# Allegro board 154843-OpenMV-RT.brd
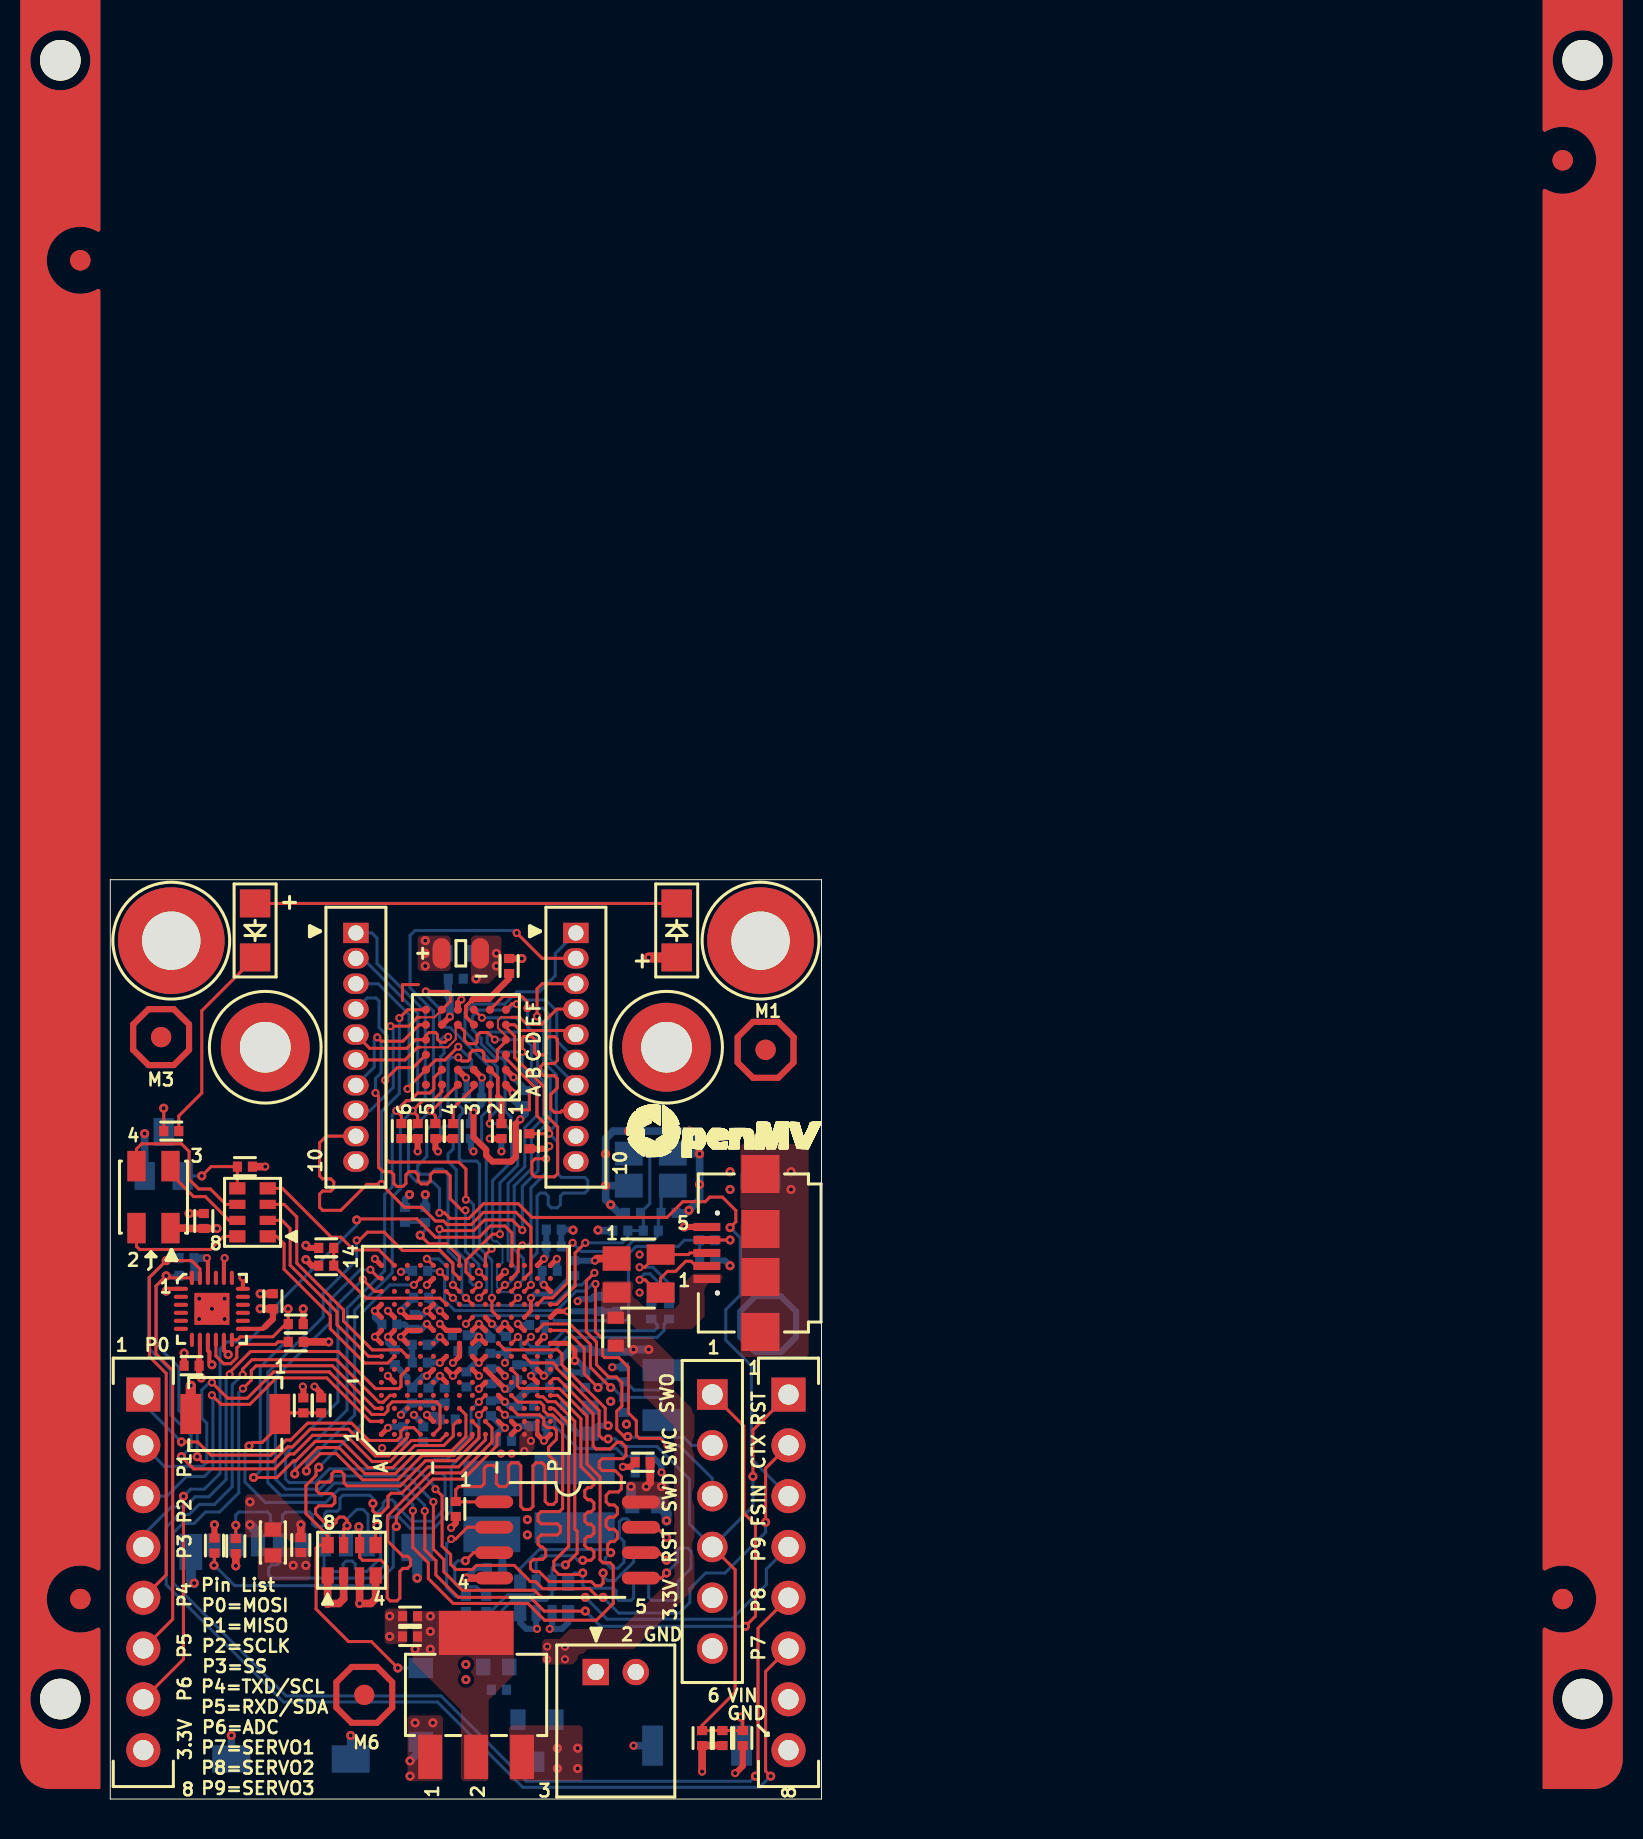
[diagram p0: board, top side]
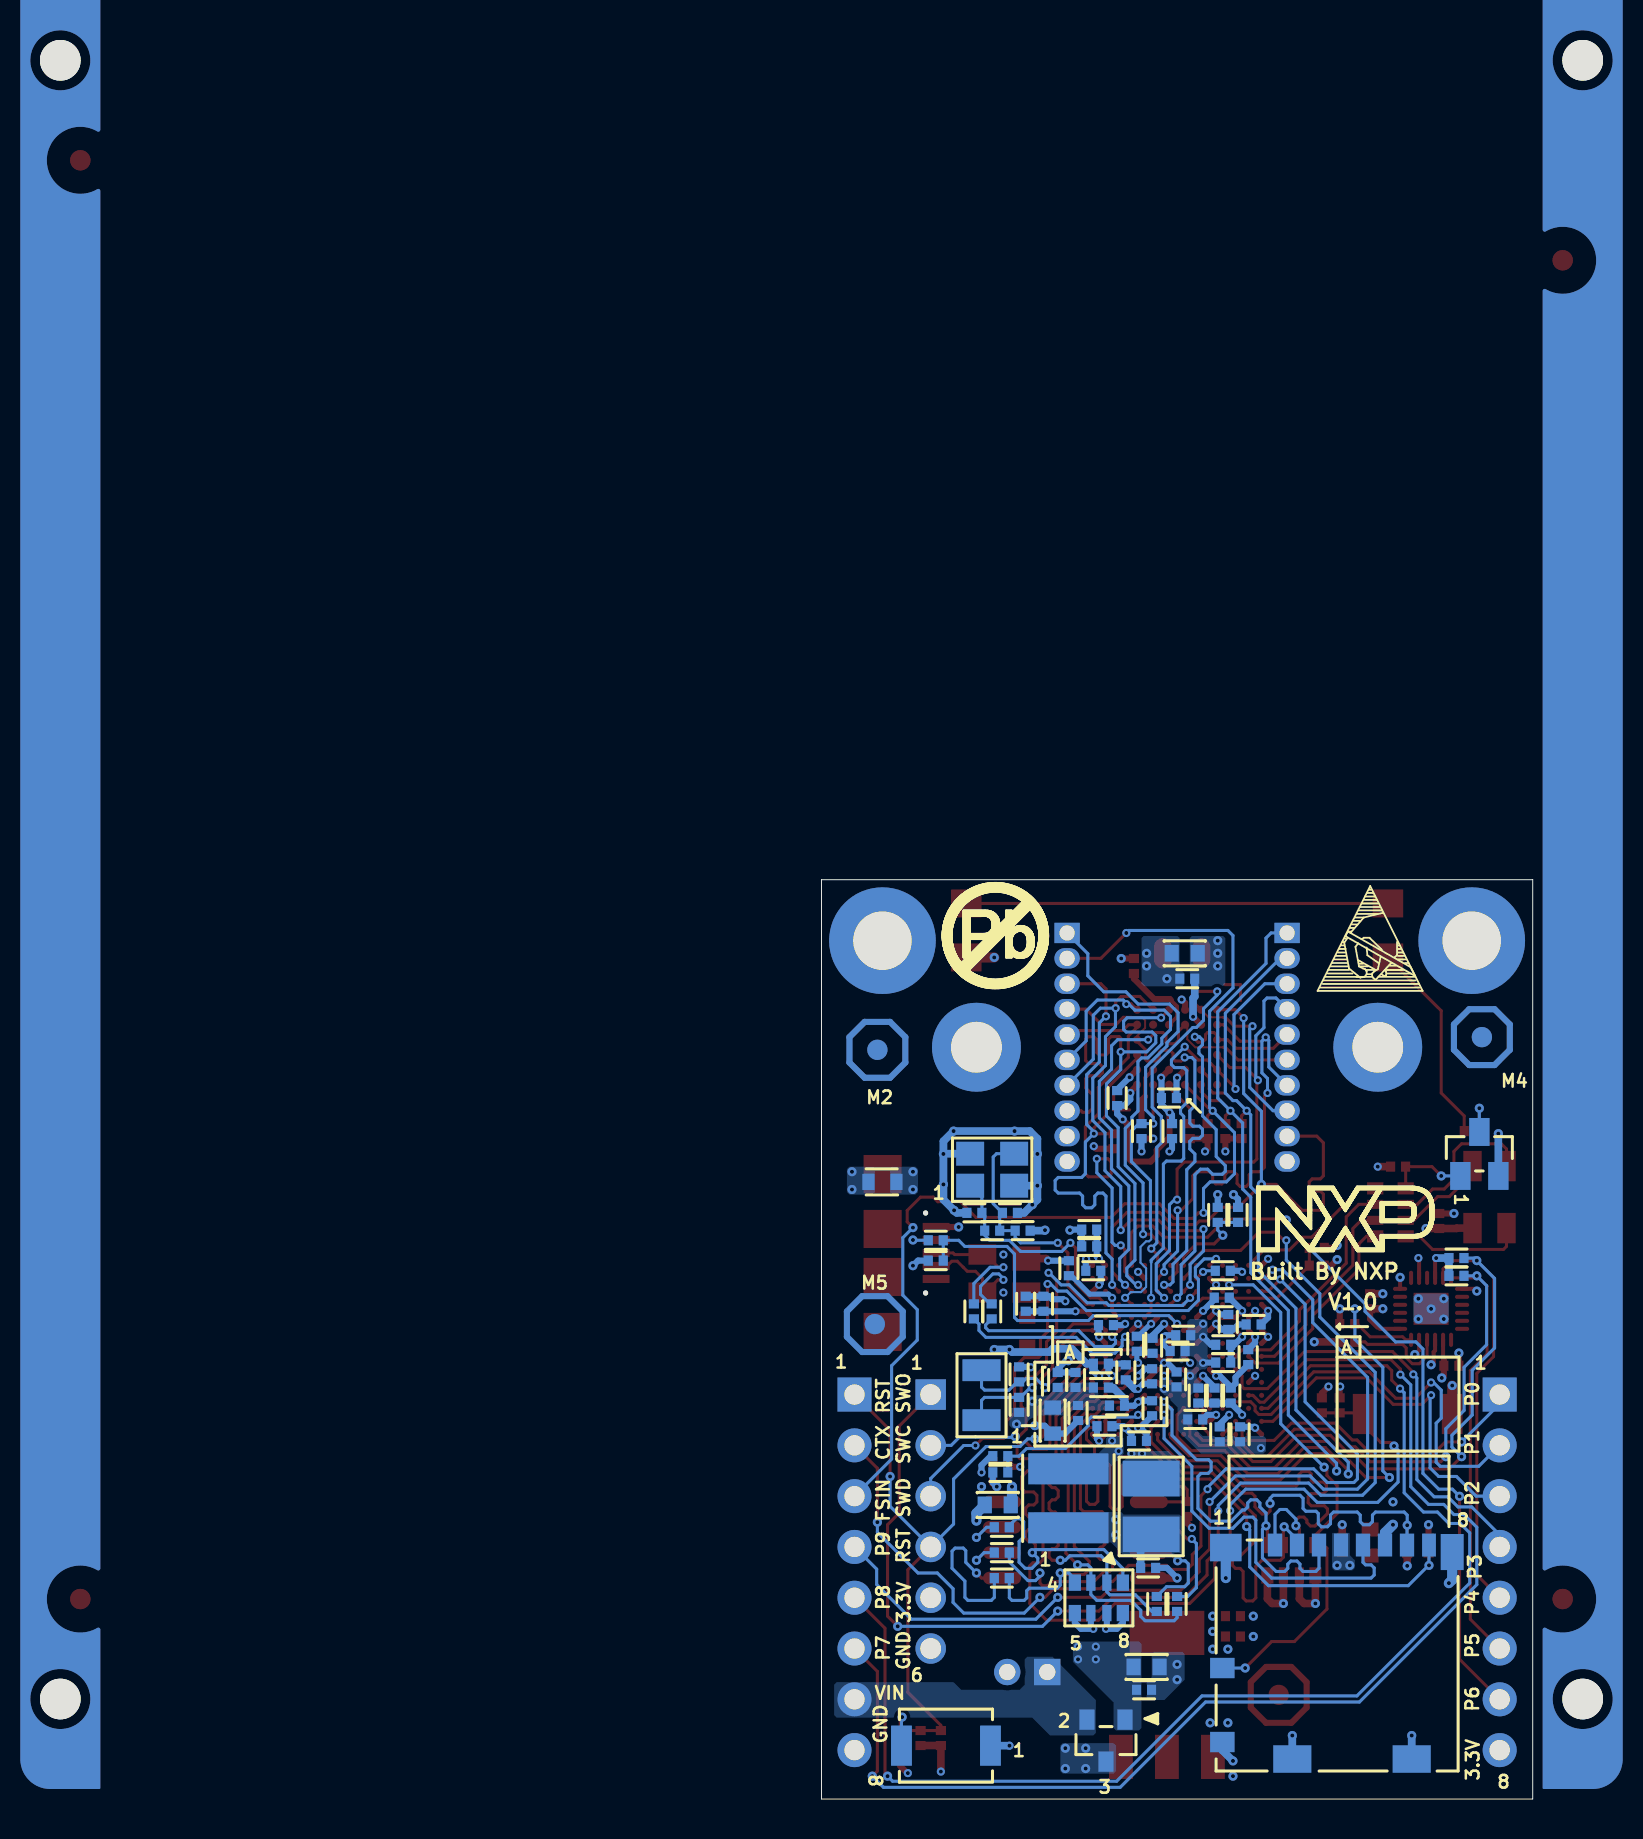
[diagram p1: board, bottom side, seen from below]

Outline 35.56 x 45.97 mm; copper layers: TOP, GND02, POWER03, BOTTOM. Coordinates in mm from the lower left corner of the outline.
Outline path: 0,45.97 35.56,45.97 35.56,0 0,0 0,45.97

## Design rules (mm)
constraint set DEFAULT: min track width 0.152
net group CSI_DATA: nets CSI_FSIN CSI_RSTB
net group FLASH_D0: nets FLASH_D0 N332353
net group FLASH_D1: nets FLASH_D1 N332366
net group FLASH_D2: nets FLASH_D2 N332379
net group FLASH_D3: nets FLASH_D3 N332392
net group FLASH_SCLK: nets FLASH_SCLK N7344830
net group USB1_DN: nets N236553 USB1_DN
net group USB1_DP: nets N236509 USB1_DP
net group POWER: nets USB_OTG2_VBUS
net group SD_DATA: nets SD_CD

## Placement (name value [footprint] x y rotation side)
C1  0.22UF  [0402_CC]  21.34 23.7 0 bottom
C2  0.22UF  [0402_CC]  15.48 21.83 180 bottom
C3  0.22UF  [0402_CC]  17.75 22.4 0 bottom
C4  0.22UF  [0402_CC]  17.81 20.98 90 bottom
C5  4.7UF  [0402_CC]  15.48 22.72 180 bottom
C6  0.1UF  [0402_CC]  15.91 20.18 270 bottom
C7  0.22UF  [0402_CC]  22.17 27.64 0 bottom
C8  0.22UF  [0402_CC]  21.97 26.42 0 bottom
C9  0.22UF  [0402_CC]  19.01 22.66 270 bottom
C10  0.22UF  [0402_CC]  16.72 20.18 270 bottom
C11  0.22UF  [0402_CC]  14.63 18.24 90 bottom
C12  0.22UF  [0402_CC]  17.48 23.19 0 bottom
C13  0.22UF  [0402_CC]  16.87 18.98 180 bottom
C14  0.22UF  [0402_CC]  15.65 18.24 90 bottom
C15  4.7UF  [0402_CC]  14.22 22.1 90 bottom
C16  0.1UF  [0402_CC]  15.1 20.18 270 bottom
C17  4.7UF  [0402_CC]  13.95 23.73 180 bottom
C18  0.1UF  [0402_CC]  15.22 23.86 90 bottom
C19  4.7UF  [0402_CC]  22.86 20.95 270 bottom
C20  0.1UF  [0402_CC]  15.54 25.07 180 bottom
C21  0.1UF  [0402_CC]  19.79 22.77 270 bottom
C22  0.22UF  [0402_CC]  23.75 20.95 270 bottom
C23  0.22UF  [0402_CC]  24.46 24.77 90 bottom
C24  4.7UF  [0402_CC]  25.35 24.77 90 bottom
C25  0.22UF  [0402_CC]  23.19 26.54 90 bottom
C26  0.1UF  [0402_CC]  29.59 3.05 270 top
C27  0.1UF  [0402_CC]  9.65 19.68 90 top
C28  0.1UF  [0402_CC]  30.61 3.05 270 top
C29  0.22UF  [0402_CC]  19.68 17.91 180 bottom
C30  4.7UF  [0402_CC]  22.17 28.47 0 bottom
C31  0.1UF  [0402_CC]  19.03 21.14 90 bottom
C32  0.22UF  [0402_CC]  21.41 18.64 0 bottom
C33  0.22UF  [0402_CC]  20.78 19.67 0 bottom
C34  4.7UF  [0402_CC]  19.03 19.54 270 bottom
C35  1uF  [0402_CC]  21.59 21.77 180 bottom
C36  33UF  [CC1210]  19.08 14.63 90 bottom
C37  0.22UF  [0402_CC]  19.23 11.56 180 bottom
C38  10UF  [0603_CC]  24 18.92 90 bottom
C39  0.1UF  [0402_CC]  22.73 19.3 90 bottom
C40  4.7UF  [0402_CC]  21.59 20.57 0 bottom
C41  0.1UF  [0402_CC]  20.35 21.34 90 bottom
C42  4.7PF  [0402_CC]  26.14 29.31 180 bottom
C43  4.7PF  [0402_CC]  27.91 29.31 0 bottom
C44  18PF  [0402_CC]  25.68 19.71 270 bottom
C45  18PF  [0402_CC]  25.68 21.23 90 bottom
C46  0.22UF  [0402_CC]  26.62 17.14 0 bottom
C47  10UF  [0603_CC]  26.75 14.71 0 bottom
C48  0.1UF  [0402_CC]  26.62 16.84 180 top
C49  0.1UF  [0402_CC]  19.43 5.46 180 bottom
C50  10UF  [0603_CC]  19.3 6.6 180 bottom
C51  1UF  [0402_CC]  14.99 8.13 180 top
C52  0.1UF  [0402_CC]  14.99 9.14 180 top
C53  0.1UF  [0402_CC]  8.13 24.89 90 top
C54  0.1UF  [0402_CC]  9.53 12.7 90 top
C55  22uF  [0603_CC]  8.13 12.83 90 top
C56  0.1UF  [0402_CC]  4.06 21.67 180 top
C57  0.1UF  [0402_CC]  17.27 41.02 0 bottom
C58  22uF  [0603_CC]  17.4 42.29 0 bottom
C59  4.7UF  [0402_CC]  20.78 35.05 90 bottom
C60  0.1UF  [0402_CC]  19.94 41.66 90 top
C61  0.1UF  [0402_CC]  17.14 33.4 270 top
C62  0.1UF  [0402_CC]  19.56 33.4 270 top
C63  0.1UF  [0402_CC]  9.27 22.86 0 top
C64  0.1UF  [0402_CC]  18.19 35.05 180 bottom
C65  0.1UF  [0402_CC]  4.67 28.91 90 top
CT1  47UF  [CC0805_OV_TANT]  17.53 42.29 0 top
D1  VSMY12850  [LED2-3_2X1_6-H1_1]  28.32 43.43 90 top
D2  150141M173100  [3528]  2.16 30.1 270 top
D3  VSMY12850  [LED2-3_2X1_6-H1_1]  7.24 43.43 270 top
D4  PMEG2005CT  [SOT23-3-0_95-3_0X1_4-H1_1]  21.34 2.92 0 bottom
FB1  330 OHM  [IND_1608]  25.27 23.37 270 top
FB2  330 OHM  [IND_1608]  32.51 30.86 180 bottom
J1  Header 6  [CON_SKT1X6_TH]  30.1 20.23 0 top
J2  USB Micro  [CON_USB5_MICROAB_0P65_SM]  32.47 27.3 90 top
J3  Header 8  [CON_1X8_SKT_2P54_TH]  1.65 20.23 0 top
J4  S2B-PH-K-S(LF)(SN)  [SIP2-2_0-S2B-PH-K-S]  25.27 6.35 0 top
J5  Header 8  [CON_1X8_SKT_2P54_TH]  33.91 20.23 0 top
J6  USD-1040310811  [SD9-SMT-SD-104031-001]  9.78 12.7 0 bottom
J7  Header 10  [CON_1X10_SKT_1P27_TH]  23.28 37.59 270 top
J8  Header 10  [CON_1X10_SKT_1P27_TH]  12.28 37.59 270 top
L1  4.7UH  [IND_VLS4012E]  23.22 15.04 90 bottom
M1  M-MARK1  [1]  32.77 37.47 0 top
M2  M-MARK1  [1]  32.77 37.47 180 bottom
M3  M-MARK1  [1]  2.54 38.1 0 top
M4  M-MARK1  [1]  2.54 38.1 180 bottom
M5  M-MARK1  [1]  32.89 23.75 180 bottom
M6  M-MARK1  [1]  12.7 5.21 0 top
NOREF  -  []  29.83 27.96 90 top
NOREF#2  -  []  242.19 35.69 0 top
NOREF#3  -  []  -58.8 -55.75 0 top
NOREF#4  -  []  21.55 12.99 90 top
NOREF#5  -  []  0 0 90 top
NOREF#6  -  []  219.33 166.5 0 top
NOREF#7  -  []  30.35 25.31 90 top
NOREF#8  -  []  29.58 31.08 0 top
NOREF#9  -  []  12.78 27.39 0 top
NOREF#10  -  []  37.72 -33.27 0 top
NOREF#11  -  []  30.35 29.3 90 top
NOREF#12  -  []  0 91.95 0 top
NOREF#13  -  []  32.5 31.26 90 top
NOREF#14  -  []  71.12 5 270 top
NOREF#15  VALUE  [unnamed#2]  3.05 42.92 0 top
NOREF#16  -  [unnamed#3]  0 0 90 top
NOREF#17  -  []  4.08 22.96 0 top
NOREF#18  -  []  32.5 23.35 90 top
NOREF#19  -  []  32.5 26.11 90 top
NOREF#20  -  []  34.73 23.53 90 top
NOREF#21  -  []  35.36 30.58 90 top
NOREF#22  -  []  71.12 0 90 top
NOREF#23  -  []  6.63 24.71 90 top
NOREF#24  -  []  23.22 13.56 90 top
NOREF#25  -  []  22.78 17.46 90 top
NOREF#26  -  []  22.01 18.24 90 top
NOREF#27  -  []  242.19 103 0 top
NOREF#28  -  []  -233.04 -241.94 0 top
NOREF#29  -  []  0 5 270 top
NOREF#30  -  []  155.45 277.88 0 top
NOREF#31  -  []  211.71 44.45 0 top
NOREF#32  -  []  21.16 16.71 0 top
NOREF#33  -  []  -26.92 -65.28 0 top
NOREF#34  -  []  0 5 0 top
NOREF#35  -  []  22.01 18.24 90 top
NOREF#36  -  []  12.78 27.46 0 top
NOREF#37  -  []  66.12 45.97 0 top
NOREF#38  -  []  210.57 -2.43 0 top
NOREF#39  -  []  6.08 22.96 90 top
NOREF#40  -  []  35.56 5 270 top
NOREF#41  VALUE  [unnamed#2]  7.75 37.59 0 top
NOREF#42  -  []  29.83 26.01 90 top
NOREF#43  -  [unnamed#4]  71.12 91.95 90 top
NOREF#44  VALUE  [unnamed#2]  27.81 37.59 0 top
NOREF#45  -  []  3.53 23.51 0 top
NOREF#46  VALUE  [unnamed#2]  32.51 42.92 0 top
NOREF#47  -  [unnamed#5]  0 91.95 90 top
NOREF#48  -  [unnamed#6]  71.12 0 90 top
Q1  SI2302CDS  [SOT-23]  2.67 32.26 180 bottom
R1  DNP  [0402_CC]  10.79 26.67 0 top
R2  10K  [0402_CC]  14.73 29.21 270 bottom
R3  10K  [0402_CC]  15.49 26.42 0 bottom
R4  10K  [0402_CC]  10.79 27.56 180 top
R5  DNP  [0402_CC]  15.75 29.21 90 bottom
R6  10K  [0402_CC]  31.62 3.05 90 top
R7  1M  [0402_CC]  27.03 28.42 0 bottom
R8  2.2M  [0402_CC]  25.5 28.42 180 bottom
R9  30.1K  [0402_CC]  26.62 16.33 0 bottom
R10  33R  [0402_CC]  26.54 12.32 0 bottom
R11  33R  [0402_CC]  27.94 24.38 270 bottom
R12  33R  [0402_CC]  27.05 24.38 270 bottom
R13  10R  [0402_CC]  3.05 33.4 180 top
R14  10K  [0402_CC]  17.27 14.5 90 top
R15  33R  [0402_CC]  26.54 11.05 180 bottom
R16  33R  [0402_CC]  17.78 9.75 270 bottom
R17  33R  [0402_CC]  18.8 9.75 270 bottom
R18  33R  [0402_CC]  26.54 13.59 180 bottom
R19  10K  [0402_CC]  6.73 31.62 0 top
R20  0  [0402_CC]  18.03 33.4 90 bottom
R21  10K  [0402_CC]  20.95 32.89 90 top
R22  10K  [0402_CC]  19.56 33.4 90 bottom
R23  10K  [0402_CC]  15.37 33.4 90 top
R24  10K  [0402_CC]  14.55 33.4 90 top
R25  10K  [0402_CC]  9.27 23.75 180 top
R26  10K  [0402_CC]  3.81 26.16 180 bottom
R27  10K  [0402_CC]  3.81 27.05 180 bottom
R28  10K  [0402_CC]  5.21 12.67 270 top
R29  10K  [0402_CC]  6.27 12.65 90 top
R30  10K  [0402_CC]  10.54 19.68 270 top
R31  10K  [0402_CC]  16.26 33.4 270 top
R32  0  [0402_CC]  29.84 27.94 180 bottom
R33  10K  [0402_CC]  29.84 26.92 0 bottom
RN1  10K  [RN8-0603]  21.69 10.06 0 bottom
RN2  220R  [RN8-0603]  7.11 29.34 90 top
RN3  10K  [RN8-0603]  12.06 11.94 0 top
SW1  SW SPST NO  [SW2_4P45_4X3_SM]  29.34 2.67 0 bottom
SW2  SW SPST NO  [SW2_4P45_4X3_SM]  6.25 19.25 180 top
U1  MIMRT105x  [BGA196_0P65_10X10MM]  17.78 22.46 90 top
U2  TLV1117LV33DCY  [SOT223]  18.29 5.21 0 top
U3  SP0503BAHT  [SOT_143]  26.42 26.28 270 top
U4  GD25Q32CSIG  [SO8-25X75-200]  22.86 12.95 270 top
U5  Camera_OV7725  [28-PINCSP2]  17.78 37.59 90 top
U6  MPU-9250  [QFN24_0P4_3P1X3P1_EP1P7X1P54]  5.08 24.51 0 top
Y1  24MHZ  [XTLOSC4_3P2X2P5MM_SM]  27.03 31.47 180 bottom
Y2  32.768KHZ  [XTAL2-3P2X1P5-SM]  27.56 20.19 90 bottom

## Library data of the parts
C1-C4 C7-C14 C22 C23 C25 C29 C32 C33 C35 C37 C46 C49 = CAP_NP: tolerance: 10%
C5 C6 C15-C21 C24 C26-C28 C30 C31 C34 C36 C39-C43 C48 C51-C54 C56 C57 C59-C65 = CAP_NP
C38 C47 C50 C55 C58 = CAP_NP: tolerance: 20%
C44 C45 = CAP_NP: tolerance: 5%
CT1 = CAP_POL: tolerance: 20%
D1 D3 = LED_0
D2 = LED_TRICOLOR_RGB_1
D4 = DUALDIODE_CC_SOT23_SHTKY
FB1 FB2 = BEAD: tolerance: 25%
J1 = CONN_HDR_0
J2 = USB_MINI_AB_RECEPTACLE
J3 J5 = CONN_HDR_8X1
J4 = CONN_HDR_2X1
J6 = MICRO CARD1
J7 J8 = CONN_HDR_2
L1 = IND_FERRITE
M1-M6 = FID-040
Q1 = MOSFET_N
R1-R6 R13 R14 R19-R33 = RES: tolerance: 5%
R7 R9 = RES: tolerance: 1%
R8 = RES
R10 R15-R18 = RES: tolerance: 5%; signal model: RES_0402_CC_DISCRETE_33R_5%_33R
R11 R12 = RES: tolerance: 5%; signal model: RES_0603_CC_DISCRETE_33R_5%_33R
RN1-RN3 = Resistor_Array
SW1 SW2 = SW2P_SPST
U1 = IMX6_BGA_196P
U2 = LM1117_FXD
U3 = SPB0503
U4 = GD25Q32C_8P
U5 = OV7725_1
U6 = MPU-9250_24P
Y1 = CRYSTAL_JXS63_0
Y2 = CRYSTAL

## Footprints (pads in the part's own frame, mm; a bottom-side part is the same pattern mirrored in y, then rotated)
1
  round 1.016 smd: 1(0,0)
28-PINCSP2
  round 0.406 smd: A1(-1.875,-2) A2(-1.875,-1.2) A3(-1.875,-0.4) A4(-1.875,0.4) A5(-1.875,1.2) A6(-1.875,2) B1(-1.125,-2) B2(-1.125,-1.2) B3(-1.125,-0.4) B4(-1.125,0.4) B5(-1.125,1.2) B6(-1.125,2) C1(-0.375,-2) C6(-0.375,2) D1(0.375,-2) D6(0.375,2) E1(1.125,-2) E2(1.125,-1.2) E3(1.125,-0.4) E4(1.125,0.4) E5(1.125,1.2) E6(1.125,2) F1(1.875,-2) F2(1.875,-1.2) F3(1.875,-0.4) F4(1.875,0.4) F5(1.875,1.2) F6(1.875,2)
0402_CC
  rect 0.457x0.508 smd: 1(-0.375,0) 2(0.375,0)
0603_CC
  rect 0.711x0.838 smd: 1(-0.65,0) 2(0.65,0)
3528
  rect 1.524x0.914 smd: 1(1.55,0.85) 2(1.55,-0.85) 3(-1.55,0.85) 4(-1.55,-0.85)
BGA196_0P65_10X10MM
  round 0.254 smd: A1(-4.225,4.225) A2(-3.575,4.225) A3(-2.925,4.225) A4(-2.275,4.225) A5(-1.625,4.225) A6(-0.975,4.225) A7(-0.325,4.225) A8(0.325,4.225) A9(0.975,4.225) A10(1.625,4.225) A11(2.275,4.225) A12(2.925,4.225) A13(3.575,4.225) A14(4.225,4.225) B1(-4.225,3.575) B2(-3.575,3.575) B3(-2.925,3.575) B4(-2.275,3.575) B5(-1.625,3.575) B6(-0.975,3.575) B7(-0.325,3.575) B8(0.325,3.575) B9(0.975,3.575) B10(1.625,3.575) B11(2.275,3.575) B12(2.925,3.575) B13(3.575,3.575) B14(4.225,3.575) C1(-4.225,2.925) C2(-3.575,2.925) C3(-2.925,2.925) C4(-2.275,2.925) C5(-1.625,2.925) C6(-0.975,2.925) C7(-0.325,2.925) C8(0.325,2.925) C9(0.975,2.925) C10(1.625,2.925) C11(2.275,2.925) C12(2.925,2.925) C13(3.575,2.925) C14(4.225,2.925) D1(-4.225,2.275) D2(-3.575,2.275) D3(-2.925,2.275) D4(-2.275,2.275) D5(-1.625,2.275) D6(-0.975,2.275) D7(-0.325,2.275) D8(0.325,2.275) D9(0.975,2.275) D10(1.625,2.275) D11(2.275,2.275) D12(2.925,2.275) D13(3.575,2.275) D14(4.225,2.275) E1(-4.225,1.625) E2(-3.575,1.625) E3(-2.925,1.625) E4(-2.275,1.625) E5(-1.625,1.625) E6(-0.975,1.625) E7(-0.325,1.625) E8(0.325,1.625) E9(0.975,1.625) E10(1.625,1.625) E11(2.275,1.625) E12(2.925,1.625) E13(3.575,1.625) E14(4.225,1.625) F1(-4.225,0.975) F2(-3.575,0.975) F3(-2.925,0.975) F4(-2.275,0.975) F5(-1.625,0.975) F6(-0.975,0.975) F7(-0.325,0.975) F8(0.325,0.975) F9(0.975,0.975) F10(1.625,0.975) F11(2.275,0.975) F12(2.925,0.975) F13(3.575,0.975) F14(4.225,0.975) G1(-4.225,0.325) G2(-3.575,0.325) G3(-2.925,0.325) G4(-2.275,0.325) G5(-1.625,0.325) G6(-0.975,0.325) G7(-0.325,0.325) G8(0.325,0.325) G9(0.975,0.325) G10(1.625,0.325) G11(2.275,0.325) G12(2.925,0.325) G13(3.575,0.325) G14(4.225,0.325) H1(-4.225,-0.325) H2(-3.575,-0.325) H3(-2.925,-0.325) H4(-2.275,-0.325) H5(-1.625,-0.325) H6(-0.975,-0.325) H7(-0.325,-0.325) H8(0.325,-0.325) H9(0.975,-0.325) H10(1.625,-0.325) H11(2.275,-0.325) H12(2.925,-0.325) H13(3.575,-0.325) H14(4.225,-0.325) J1(-4.225,-0.975) J2(-3.575,-0.975) J3(-2.925,-0.975) J4(-2.275,-0.975) J5(-1.625,-0.975) J6(-0.975,-0.975) J7(-0.325,-0.975) J8(0.325,-0.975) J9(0.975,-0.975) J10(1.625,-0.975) J11(2.275,-0.975) J12(2.925,-0.975) J13(3.575,-0.975) J14(4.225,-0.975) K1(-4.225,-1.625) K2(-3.575,-1.625) K3(-2.925,-1.625) K4(-2.275,-1.625) K5(-1.625,-1.625) K6(-0.975,-1.625) K7(-0.325,-1.625) K8(0.325,-1.625) K9(0.975,-1.625) K10(1.625,-1.625) K11(2.275,-1.625) K12(2.925,-1.625) K13(3.575,-1.625) K14(4.225,-1.625) L1(-4.225,-2.275) L2(-3.575,-2.275) L3(-2.925,-2.275) L4(-2.275,-2.275) L5(-1.625,-2.275) L6(-0.975,-2.275) L7(-0.325,-2.275) L8(0.325,-2.275) L9(0.975,-2.275) L10(1.625,-2.275) L11(2.275,-2.275) L12(2.925,-2.275) L13(3.575,-2.275) L14(4.225,-2.275) M1(-4.225,-2.925) M2(-3.575,-2.925) M3(-2.925,-2.925) M4(-2.275,-2.925) M5(-1.625,-2.925) M6(-0.975,-2.925) M7(-0.325,-2.925) M8(0.325,-2.925) M9(0.975,-2.925) M10(1.625,-2.925) M11(2.275,-2.925) M12(2.925,-2.925) M13(3.575,-2.925) M14(4.225,-2.925) N1(-4.225,-3.575) N2(-3.575,-3.575) N3(-2.925,-3.575) N4(-2.275,-3.575) N5(-1.625,-3.575) N6(-0.975,-3.575) N7(-0.325,-3.575) N8(0.325,-3.575) N9(0.975,-3.575) N10(1.625,-3.575) N11(2.275,-3.575) N12(2.925,-3.575) N13(3.575,-3.575) N14(4.225,-3.575) P1(-4.225,-4.225) P2(-3.575,-4.225) P3(-2.925,-4.225) P4(-2.275,-4.225) P5(-1.625,-4.225) P6(-0.975,-4.225) P7(-0.325,-4.225) P8(0.325,-4.225) P9(0.975,-4.225) P10(1.625,-4.225) P11(2.275,-4.225) P12(2.925,-4.225) P13(3.575,-4.225) P14(4.225,-4.225)
CC0805_OV_TANT
  oval 0.889x1.524 smd: 1(-0.965,0) 2(0.965,0)
CC1210
  rect 1.778x2.845 smd: 1(-1.397,0) 2(1.397,0)
CON_1X8_SKT_2P54_TH
  rect 1.702x1.702 hole 1.016: 1(0,0)
  round 1.702 hole 1.016: 2(0,-2.54) 3(0,-5.08) 4(0,-7.62) 5(0,-10.16) 6(0,-12.7) 7(0,-15.24) 8(0,-17.78)
CON_1X10_SKT_1P27_TH
  rect 1.016x1.27 hole 0.762: 1(-5.715,0)
  oval 1.016x1.27 hole 0.762: 2(-4.445,0) 3(-3.175,0) 4(-1.905,0) 5(-0.635,0) 6(0.635,0) 7(1.905,0) 8(3.175,0) 9(4.445,0) 10(5.715,0)
CON_SKT1X6_TH
  rect 1.524x1.524 hole 1.041: 1(0,0)
  round 1.524 hole 1.041: 2(0,-2.54) 3(0,-5.08) 4(0,-7.62) 5(0,-10.16) 6(0,-12.7)
CON_USB5_MICROAB_0P65_SM
  round 0.254 hole 0.559 unplated: (-2,2.115) (2,2.115)
  rect 0.406x1.346 smd: 1(-1.3,2.64) 2(-0.65,2.64) 3(0,2.64) 4(0.65,2.64) 5(1.3,2.64)
  rect 1.905x1.905 smd: S1(-3.95,-0.035) S2(3.95,-0.035) S3(-1.2,-0.035) S4(1.2,-0.035)
IND_1608
  rect 0.61x0.813 smd: 1(-0.7,0) 2(0.7,0)
IND_VLS4012E
  rect 1.549x4.013 smd: 1(-1.475,0) 2(1.475,0)
LED2-3_2X1_6-H1_1
  rect 1.397x1.524 smd: 1(-1.35,0) 2(1.35,0)
QFN24_0P4_3P1X3P1_EP1P7X1P54
  oval 0.711x0.203 smd: 1(-1.55,1) 2(-1.55,0.6) 3(-1.55,0.2) 4(-1.55,-0.2) 5(-1.55,-0.6) 6(-1.55,-1) 13(1.55,-1) 14(1.55,-0.6) 15(1.55,-0.2) 16(1.55,0.2) 17(1.55,0.6) 18(1.55,1)
  oval 0.203x0.711 smd: 7(-1,-1.55) 8(-0.6,-1.55) 9(-0.2,-1.55) 10(0.2,-1.55) 11(0.6,-1.55) 12(1,-1.55) 19(1,1.55) 20(0.6,1.55) 21(0.2,1.55) 22(-0.2,1.55) 23(-0.6,1.55) 24(-1,1.55)
  rect 1.753x1.6 smd: 25(0,0)
RN8-0603
  rect 0.61x0.813 smd: 1(-1.2,-0.76) 4(1.2,-0.76) 5(1.2,0.76) 8(-1.2,0.76)
  rect 0.457x0.813 smd: 2(-0.4,-0.76) 3(0.4,-0.76) 6(0.4,0.76) 7(-0.4,0.76)
SD9-SMT-SD-104031-001
  rect 0.711x1.143 smd: 1(3.105,0) 2(2.005,0) 3(0.905,0) 4(-0.195,0) 5(-1.295,0) 6(-2.395,0) 7(-3.495,0)
  rect 0.686x1.143 smd: 8(-4.595,0)
  rect 1.219x1.016 smd: 9(5.74,9.85) 10(5.74,6.15)
  rect 1.575x1.372 smd: 11(5.565,0.125)
  rect 1.143x1.803 smd: 12(-5.755,0.35)
  rect 1.905x1.372 smd: 13(-3.73,10.7) 14(2.24,10.7)
SIP2-2_0-S2B-PH-K-S
  rect 1.321x1.321 hole 0.813: 1(-1,0)
  round 1.321 hole 0.813: 2(1,0)
SO8-25X75-200
  oval 0.635x1.905 smd: 1(-1.905,-3.67) 2(-0.635,-3.67) 3(0.635,-3.67) 4(1.905,-3.67) 5(1.905,3.67) 6(0.635,3.67) 7(-0.635,3.67) 8(-1.905,3.67)
SOT23-3-0_95-3_0X1_4-H1_1
  rect 0.762x1.016 smd: 1(-0.95,-1.05) 2(0.95,-1.05) 3(0,1.05)
SOT223
  rect 1.194x2.21 smd: 1(-2.3,-3.1) 2(0,-3.1) 3(2.3,-3.1)
  rect 3.734x2.21 smd: 4(0,3.1)
SOT-23
  rect 1.016x1.397 smd: 1(-0.95,-1.1) 2(0.95,-1.1) 3(0,1.1)
SOT_143
  rect 1.219x1.397 smd: 1(-0.75,-1.1)
  rect 1.016x1.397 smd: 2(0.95,-1.1) 3(0.95,1.1) 4(-0.95,1.1)
SW2_4P45_4X3_SM
  rect 1.041x2.007 smd: 1(-2.225,0) 2(2.225,0)
unnamed#2
  round 5.334 hole 2.921: 1(0,0)
unnamed#3
  round 2.032 hole 2.032 unplated: (5,2.5)
  round 1.016 smd: (10,1.5) (10,1.5)
unnamed#4
  round 1.016 smd: (-10,-1.5) (-10,-1.5)
  round 2.032 hole 2.032 unplated: (-5,-2.5)
unnamed#5
  round 1.016 smd: (-15,1.5) (-15,1.5)
  round 2.032 hole 2.032 unplated: (-5,2.5)
unnamed#6
  round 2.032 hole 2.032 unplated: (5,-2.5)
  round 1.016 smd: (10,-1.5) (10,-1.5)
XTAL2-3P2X1P5-SM
  rect 1.092x1.905 smd: 1(-1.25,0) 2(1.25,0)
XTLOSC4_3P2X2P5MM_SM
  rect 1.397x1.194 smd: 1(-1.1,-0.8) 2(1.1,-0.8) 3(1.1,0.8) 4(-1.1,0.8)

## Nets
GND: C1.2 C2.2 C3.2 C4.2 C5.2 C6.2 C7.2 C8.2 C9.2 C10.2 C11.2 C12.2 C13.2 C14.2 C15.2 C16.2 C17.2 C18.2 C19.2 C20.2 C21.2 C22.2 C23.2 C24.2 C25.2 C26.2 C27.2 C28.2 C29.2 C30.2 C31.2 C32.2 C33.2 C34.2 C35.2 C36.2 C37.2 C38.2 C39.2 C40.2 C41.2 C42.2 C43.2 C44.2 C45.2 C46.2 C47.2 C48.2 C49.2 C50.2 C51.2 C52.2 C53.2 C54.2 C55.2 C56.2 C57.2 C58.2 C59.2 C60.2 C61.2 C62.2 C63.2 C64.2 C65.2 CT1.2 FB2.2 J1.6 J2.5 J4.2 J5.8 J6.6(VSS) J6.9 J6.11 J6.12 J6.13 J6.14 J7.9 J7.10 Q1.2(SOURCE) R3.1 R4.2 R5.2 R8.2 R19.2 R31.2 SW1.1 SW2.2(SW2) U1.A1 U1.A8 U1.A9 U1.A10 U1.A11 U1.A14 U1.B5 U1.B8 U1.B9 U1.B10 U1.C8 U1.C9 U1.C10 U1.D9 U1.D10 U1.E2 U1.E10 U1.E11 U1.E13 U1.G7 U1.G8 U1.H7 U1.H8 U1.J7 U1.J8 U1.K2 U1.K6 U1.K9 U1.K13 U1.L9 U1.N1 U1.N2 U1.N5 U1.N8 U1.P1 U1.P14 U2.1 U3.1 U4.4 U5.B1 U5.B4 U5.F4 U6.9 U6.11 U6.18 U6.20 Y1.2 Y1.4(GND2)
VDD_3V3: C1.1 C6.1 C7.1 C8.1 C15.1 C16.1 C17.1 C18.1 C20.1 C21.1 C29.1 C30.1 C31.1 C32.1 C33.1 C34.1 C40.1 C41.1 C47.1 C48.1 C51.1 C52.1 C53.1 C54.1 C55.1 C56.1 C57.1 C58.1 C65.1 CT1.1 D1.1 D2.1 J1.5 J3.8 J6.4 J8.10 R1.1 R2.1 R6.1 R9.2 R14.1 R20.1 R21.1 R22.1 R23.1 R24.1 R25.1 R26.1 R27.1 R28.1 R29.1 R30.1 R33.2 RN1.5 RN1.6 RN1.7 RN1.8(PIN8) RN3.1 RN3.2 RN3.3 RN3.4 U1.E6 U1.E9 U1.F5 U1.F10 U1.J6 U1.J10 U1.K4 U1.K5(NVCC_SD1) U1.L1 U1.L2 U1.M9 U1.N14 U1.P12 U2.2(VOUT) U2.4 U4.8 U5.E5 U6.1 U6.8(VDDIO) U6.13 U6.22
VDD_SOC_IN: C2.1 C3.1 C4.1 C5.1 C9.1 C10.1 C11.1 C12.1 C13.1 C14.1 C36.1 C37.1 L1.1 U1.F6 U1.F7 U1.F8 U1.F9 U1.G6 U1.G9 U1.H6 U1.H9 U1.J5 U1.J9
9250_INT: R25.2 U1.G2 U6.12
9250_SCL: J3.5 R27.2 U1.F1 U6.23
9250_SDA: J3.6 R26.2 U1.C1 U6.24
ADC/PWM: J3.7 U1.L14
BOOT_MODE0: R1.2 R4.1 U1.F11
BOOT_MODE1: R2.2 R5.1 U1.G14
CAN2_RX/QT2_T3: J5.4 U1.A13
CAN2_TX: J5.2 U1.A12
CSI_D2: J8.8 U1.J14 U5.F5
CSI_D3: J7.7 U1.G12 U5.F2
CSI_D4: J8.5 U1.H11 U5.D6
CSI_D5: J7.4 U1.H12 U5.D1
CSI_D6: J8.7 U1.J13 U5.E6
CSI_D7: J7.5 U1.L13 U5.E1
CSI_D8: J8.9 U1.M13 U5.F6
CSI_D9: J7.6 U1.H13 U5.F1
CSI_FSIN: J5.3 J7.2 R31.1 U5.A4
CSI_HSYNC: J8.3 U1.K10 U5.B6
CSI_MCLK: J7.8 U1.K12 U5.F3(XCLK)
CSI_PIXCLK: J8.6 U1.L12 U5.E4
CSI_PWDN: J7.3 R21.2 U1.M12 U5.C1
CSI_RSTB: J7.1 R22.2 U1.L11 U5.A2
CSI_VSYNC: J8.4 U1.J12 U5.C6
EP: U6.25
FLASH_CS: R14.2 U1.L3 U4.1
FLASH_D0: R15.2 RN1.4 U1.P3
FLASH_D1: R16.2 RN1.3 U1.N4
FLASH_D2: R17.2 RN1.2 U1.P4
FLASH_D3: R18.2 RN1.1 U1.P5
FLASH_SCLK: R10.2 U4.6
GPANAIO: U1.N10
LED_B: RN2.1 U1.B7
LED_G: RN2.3 U1.C7
LED_IR: RN2.4 U1.B14
LED_R: RN2.2 U1.A7
LPSPI1_PCS0: J3.4 U1.C6
LPSPI1_SCK: J3.3 U1.A2
LPSPI1_SDI: J3.2 U1.E1
LPSPI1_SDO: J3.1 U1.D1
RAW_5V: D4.2 J4.1 J5.7
RST_B: C26.1 C28.1 J1.4 J5.1 R6.2 SW1.2(SW2) U1.M7
SCCB_SCL: J8.1 R23.2 U1.H1 U5.A5
SCCB_SDA: J8.2 R24.2 U1.G3 U5.B5
SD_CD: J6.10 RN3.8(PIN8) U1.D13
SD_CLK: J6.5 U1.J3
SD_CMD: J6.3 RN3.5 U1.J4
SD_D0: J6.7 R29.2 U1.J1
SD_D1: J6.8 R28.2 U1.K1
SD_D2: J6.1 RN3.7 U1.H2
SD_D3: J6.2 RN3.6 U1.J2
SWD_CLK: J1.2 U1.F12
SWD_DIO: J1.3 U1.E14
SWD_SWO: J1.1 U1.G13
UART4_RX/QT2_T1: J5.5 U1.A3
UART4_TX/QT2_T0: J5.6 U1.B4
USB1_DN: R12.2 U1.M8
USB1_DP: R11.2 U1.L8
USB_5V: C35.1 C49.1 C50.1 D4.1 FB1.2 U1.N6
USB_OTG1_ID: R32.2 R33.1 U1.H10
USB_OTG2_VBUS: U1.P6
USER BUTTON: C27.1 R30.2 SW2.1 U1.L6
N80926: C38.1 C39.1 U1.K8
N169826: R3.2 U1.F13
N229181: C19.1 C22.1 U1.P8
N229229: C42.1 R7.1 R8.1 U1.P11 Y1.3
N229241: L1.2 U1.M1 U1.M2
N229269: C23.1 C24.1 U1.P10
N229297: C43.1 R7.2 U1.N11 Y1.1
N229465: C25.1 U1.M10
N229469: C44.1 U1.N9 Y2.1
N229477: C46.1 R9.1 U1.K3
N229533: C45.1 U1.P9 Y2.2
N236415: FB2.1 J2.S1 J2.S2 J2.S3 J2.S4(SHLD4)
N236477: J2.4 R32.1
N236509: J2.3 R11.1 U3.4(CATHODE3)
N236553: J2.2 R12.1 U3.3
N236589: FB1.1 J2.1 U3.2
N246574: C59.1 C64.1 R20.2 U5.A1 U5.B3
N246626: C60.1 U5.E3
N246706: C61.1 U5.A3
N246726: C62.1 U5.B2
N257264: C63.1 U6.10
N263637: D3.2(CATHODE) R13.1
N263641: D2.2 RN2.8(PIN8)
N263645: D2.3(R) RN2.7
N263649: D2.4 RN2.6
N263673: Q1.3 R13.2
N263791: Q1.1 R19.1 RN2.5
N264381: D1.2(CATHODE) D3.1
N332353: R15.1 U4.5
N332366: R16.1 U4.2
N332379: R17.1 U4.3(W\P\_IO2)
N332392: R18.1 U4.7
N670164: D4.3(C) U2.3
N7344830: R10.1 U1.L4

Pads without a net: M1 1; M2 1; M3 1; M4 1; M5 1; M6 1; NOREF#15 1; NOREF#41 1; NOREF#44 1; NOREF#46 1; U1 A4 A5 A6 B1 B2 B3 B6 B11 B12 B13 C2 C3 C4 C5 C11 C12 C13 C14 D2 D3 D4 D5 D6 D7 D8 D11 D12 D14 E3 E4 E5 E7 E8 E12 F2 F3 F4 F14 G1 G4 G5 G10 G11 H3 H4 H5 H14 J11 K7 K11 K14 L5 L7 L10 M3 M4 M5 M6 M11 M14 N3 N7 N12 N13 P2 P7 P13; U5 A6 E2; U6 2 3 4 5 6 7 14 15 16 17 19 21

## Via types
v1: diameter 0.457, hole 0.203, TOP to BOTTOM, 138 vias
v2: diameter 0.406, hole 0.203, TOP to BOTTOM, 160 vias

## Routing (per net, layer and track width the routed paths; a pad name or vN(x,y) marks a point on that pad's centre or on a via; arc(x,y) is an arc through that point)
GND: length 98.6
  TOP w0.203: U1.N2 U1.N1 ; U6.9 4.88,22.43 4.95,22.35 4.95,21.84 v1(5.08,21.72) ; v1(6.63,26.09) U6.18 ; v1(5.89,22.23) 5.68,22.44 U6.11 ; U6.20 5.68,27.02 v2(5.71,27.05)
  TOP w0.254: U1.K13 v2(19.73,26.36) ; U1.A9 v2(13.23,23.11) U1.A8 ; U1.E10 v2(15.83,24.41) U1.E11 ; U1.D10 U1.C10 v2(14.53,24.41) ; U1.K2 v2(19.73,18.56) ; U1.A1 v2(13.88,18.56) ; U1.N5 v2(21.03,21.16) ; U1.J7 v2(18.43,21.81) U1.H7 ; U1.G8 U1.G7 v2(17.13,21.81) ; U1.E2 v2(15.83,19.21) ; U1.B8 v2(13.88,23.11) U1.B9 ; U1.B5 v2(13.88,21.16) ; U1.K6 v2(19.73,21.16) ; U1.B10 v2(13.88,24.41) ; U1.A10 v2(13.23,24.41) U1.A11 ; U1.C8 v2(14.53,23.11) U1.C9 U1.D9 ; U1.K9 v2(19.73,23.76) U1.L9 ; U1.H8 v2(18.43,23.11) U1.J8 ; U1.P14 v2(22.33,27.01) ; U1.P1 v2(21.68,17.91) U1.N1 ; v2(15.83,25.71) U1.E13 ; U1.N8 v2(21.68,23.11) ; U1.A14 v2(13.23,27.01)
  TOP w0.305: C56.2 v1(3.69,22.3) ; U5.B4 v2(17.78,36.07) ; v2(9.63,20.62) 9.65,20.6 C27.2 ; C65.2 v1(3.94,29.28) ; J2.5 v1(28.7,28.6) ; C60.2 v1(20.57,42.03) ; v2(17.55,39.98) 17.38,39.81 U5.F4 ; v2(18.97,33.03) C62.2 ; v1(9.78,27.69) 9.91,27.56 R4.2 ; v2(16.38,32.38) 16.26,32.51 R31.2 C61.2 ; v2(25.63,16.61) 26.02,16.61 C48.2 ; U5.B1 v2(20.16,36.09)
  TOP w0.381: C53.2 v1(7.49,25.27) ; 19.19,11.05 v1(17.78,11.05) ; U3.1 24.33,27.03 v2(24.23,26.92) ; R19.2 v2(7.75,31.62) ; C63.2 v1(10.92,22.86) ; C28.2 C26.2 v2(29.59,1.37) ; C54.2 v1(9.53,13.72)
  TOP w0.508: SW2.2 v1(4.02,20.68)
  BOTTOM w0.254: C3.2 18.43,22.7 v2(18.43,23.11) ; C9.2 19.69,22.29 C21.2 19.79,21.88 v2(19.73,21.81)
  BOTTOM w0.305: C14.2 15.65,18.74 v2(15.18,19.21) ; v2(13.23,24.41) 13.23,24.08 C17.2 ; C8.2 22.35,27 v2(22.33,27.01) ; v2(21.68,17.91) 21.79,18.02 C32.2 ; C13.2 16.27,19.21 v2(15.83,19.21) ; C2.2 C5.2 14.93,22.72 v2(14.53,23.11) ; C4.2 18.26,21.81 v2(18.43,21.81) ; v2(17.78,36.07) 17.81,36.04 C64.2 ; v2(13.88,23.11) 13.88,22.82 C15.2 ; C29.2 19.31,18.26 19.61,18.56 19.64,18.56 ; v2(21.03,21.16) 21.21,21.35 C35.2 20.4,21.77 C41.2 ; C37.2 18.29,11.56 v1(17.78,11.05) ; v2(24.23,26.92) 24.23,26.92 C25.2 ; C34.2 19.64,18.56 ; 19.64,18.56 v2(19.73,18.56) ; C59.2 20.78,35.47 v2(20.16,36.09) ; v1(23.14,28.45) 23.11,28.47 C30.2 C7.2 ; v2(23.37,24.89) 23.47,24.99 24.03,24.99 24.17,25.14 C23.2 C24.2 ; C45.2 25.11,21.61 v2(25.1,21.59) ; R3.1 14.58,26.42 v2(14.53,26.36) ; C11.2 13.93,18.61 v2(13.88,18.56) ; v2(19.73,21.16) 19.38,21.52 C31.2 ; C12.2 18.35,23.19 v2(18.43,23.11) ; v2(15.83,24.41) 15.65,24.23 C18.2 ; C10.2 C6.2 C16.2 14.53,19.24 v2(14.53,19.21) ; C1.2 21.71,23.14 v2(21.68,23.11) ; v2(14.53,24.41) 14.53,24.43 C20.2 ; C46.2 27.1,17.14 27.56,16.69 v2(27.56,16.33) ; R5.2 v1(15.75,30.23)
  BOTTOM w0.381: v1(24.38,28.45) 24.41,28.42 R8.2 ; v1(1.72,33.27) Q1.2 ; J6.13 v1(6.05,3.17) ; v1(29.46,32.26) v1(29.46,30.73) 29.46,29.97 v1(28.93,29.44) 28.8,29.31 C43.2 ; v1(29.46,32.26) 29.45,32.27 Y1.4 ; v1(29.46,32.26) 29.46,32.89 v1(28.96,33.4) v1(25.91,33.4) 25.15,33.4 24.77,33.02 v1(24.77,32.26) v1(24.77,30.67) ; v1(14.99,1.91) 15.52,2.44 J6.9 ; v1(24.77,30.67) 24.77,29.97 v1(25.02,29.72) 25.43,29.31 C42.2 ; v1(24.77,30.67) Y1.2 ; SW1.1 v2(26.16,2.67) ; J6.14 v1(12.02,3.17)
  BOTTOM w0.508: J6.6 7.38,13.32 v1(6.99,13.72) ; v1(27.81,13.92) 27.81,14.29 C47.2 ; J6.12 4.02,10.96 v1(4.19,10.79) ; J6.11 v1(15.34,11.05)
  vias: v1(6.99,14.86) v1(13.97,9.14) v1(13.97,8.13) v1(14.99,1.14) v1(15.24,3.81) v1(16.13,3.81) v1(17.78,6.73) v1(17.78,5.97) v1(18.29,41.02) v1(19.3,42.29) v1(19.3,41.66) v1(25.02,19.89) v1(25.81,18.75) v1(30.99,31.37) v1(30.99,30.48) v2(19.53,17.27) v2(20.07,17.27) v2(26.46,27.23) v2(26.46,25.33)
VDD_3V3: length 62.3
  TOP w0.203: U6.1 2.9,25.51 v1(2.79,25.4) ; U6.13 7.64,23.51 7.75,23.62 ; U6.8 4.48,22.01 4.44,21.97 ; U6.22 4.88,27 v2(4.83,27.05)
  TOP w0.254: v2(16.48,21.16) U1.F5 ; U1.E9 v2(15.83,23.76) ; U1.L1 v2(20.38,18.56) U1.L2 ; U1.N14 v2(21.68,27.01) ; U1.J10 v2(19.08,23.76) ; U1.J6 U1.K5 v2(19.73,20.51) ; U1.F10 v2(16.48,24.41) ; v2(21.68,25.71) U1.P12 ; U1.K4 v2(19.73,19.86) ; U1.M9 v2(20.38,23.76) ; U1.E6 v2(15.83,21.16)
  TOP w0.305: v1(9.78,26.97) 10.08,26.67 R1.1 ; v2(10.21,20.62) 10.54,20.29 R30.1 ; U5.E5 v2(16.98,39.12) ; R25.1 v1(9.65,24.51) ; v2(15.37,32.38) R23.1 R24.1 ; R6.1 31.62,1.65 31.27,1.3 v2(31.24,1.3) ; C53.1 8.13,24 7.75,23.62 ; R21.1 21.82,32.52 v2(21.95,32.64) ; v1(4.55,21.06) 4.44,21.16 C56.1 4.44,21.97 ; v2(17.04,13.56) 17.27,13.8 R14.1 ; R28.1 v1(5.21,13.72)
  TOP w0.381: R29.1 v1(6.27,11.66) ; v1(5.33,28.53) C65.1 3.81,28.53 3.79,28.55 D2.1 ; v1(26.8,15.62) 26.99,15.82 C48.1 ; RN3.2 11.67,10.01 11.43,9.78 v1(10.87,9.78) RN3.1 ; C53.1 v1(7.49,24.52) ; RN3.4 13.26,10.01 13.03,9.78 v1(12.46,9.78) RN3.3
  TOP w0.508: D1.1 v1(26.92,42.08)
  BOTTOM w0.254: v2(19.08,23.76) 19.11,23.76 19.73,23.14 C21.1
  BOTTOM w0.305: v2(16.48,21.16) 15.91,20.59 C6.1 ; v2(21.68,27.01) 21.8,27.13 C7.1 C30.1 ; C8.1 21.6,25.79 v2(21.68,25.71) ; v2(15.83,21.16) 15.65,21.16 15.1,20.61 C16.1 14.86,20.79 14.86,21.09 C15.1 ; C32.1 20.46,18.64 v2(20.38,18.56) 20.06,18.24 C29.1 ; R9.2 26.99,15.82 v1(26.8,15.62) ; R2.1 14.73,30 v1(14.96,30.23) ; C31.1 19.48,20.77 v2(19.73,20.51) ; v2(20.38,23.76) 20.44,23.7 C1.1 ; R33.2 30.73,26.92 v1(30.99,26.67) ; v2(15.83,23.76) 15.55,23.48 C18.1 14.96,23.48 14.71,23.73 C17.1 ; C20.1 15.92,24.97 v2(16.48,24.41) ; R22.1 v2(19.56,32.38) ; RN1.8 20.49,8.81 20.8,8.51 v2(21.34,8.51) 21.29,8.55 RN1.7 ; RN1.5 22.89,8.81 22.59,8.51 v2(21.97,8.51) 22.09,8.63 RN1.6 ; C33.1 19.92,19.67 v2(19.73,19.86) 19.68,19.92 C34.1 ; R20.1 18.03,32.51 v2(18.16,32.38)
  BOTTOM w0.381: C40.1 20.98,20.57 20.41,20 C33.1 ; v2(19.73,20.51) 19.9,20.51 C41.1 ; C57.1 16.9,40.13 16.98,40.04 v2(16.98,39.12) ; v2(4.83,27.05) R27.1 R26.1
  BOTTOM w0.508: C47.1 26.04,14.77 v1(26.04,15.62)
  vias: v1(9.14,11.68) v1(9.78,11.68) v1(15.24,7.49) v1(15.75,42.93) v1(15.75,42.29) v1(15.75,41.66) v1(16,9.14) v1(16,8.38) v1(16,7.49) v1(27.56,15.62)
VDD_SOC_IN: length 9.1
  TOP w0.254: U1.H6 v2(18.43,21.16) ; U1.G6 v2(17.13,21.16) U1.F6 ; U1.F8 v2(16.48,23.11) ; U1.F7 v2(16.48,21.81) ; U1.H9 v2(18.43,23.76) U1.J9 ; v2(18.43,20.51) U1.J5 ; U1.G9 U1.F9 v2(16.48,23.76)
  BOTTOM w0.305: v2(16.48,21.81) 16.47,21.83 C2.1 ; C9.1 19.01,23.18 v2(18.43,23.76) ; C5.1 16.08,22.72 v2(16.48,23.11)
  BOTTOM w0.381: C36.1 19.6,12.71 C37.1
  vias: v1(20.85,13.97) v1(20.85,13.21) v2(13.59,17.55)
9250_INT: length 25.9
  TOP w0.152: v1(8.89,24.51) 8.9,24.51 R25.2 8.76,23.75 8.13,23.11 6.5,23.11 6.35,22.96 U6.12 ; U1.G2 17.35,18.89 17.14,18.68 17.14,18.14 16.68,17.68 15.23,17.68 14.12,16.57 12.89,16.57 11.58,17.88 10.24,17.88 9.27,16.91 9.17,16.91 8.33,16.08 v1(7.16,16.08)
  BOTTOM w0.152: v1(7.16,16.08) 7.49,16.41 7.49,21.59 8.89,22.99 v1(8.89,24.51)
9250_SCL: length 47.6
  TOP w0.152: J3.5 2.79,11.21 2.79,21.29 1.96,22.12 1.96,26.09 v1(2.79,26.92) 4.06,26.92 4.48,26.51 U6.23 ; v1(3.56,17.12) 4.17,16.51 8.23,16.51 8.98,17.26 9.19,17.26 10.12,18.19 11.79,18.19 13.1,16.88 13.99,16.88 15.05,17.93 16.5,17.93 U1.F1
  BOTTOM w0.152: v1(3.56,17.12) 4.04,17.6 4.04,18.19 3.02,19.2 3.02,21.44 1.91,22.56 1.91,26.04 v1(2.79,26.92) 2.92,27.05 R27.2
9250_SDA: length 44.2
  TOP w0.152: J3.6 3.12,8.99 3.12,21.42 2.28,22.26 2.28,25.65 v1(2.79,26.16) 2.89,26.06 U6.24 ; U1.C1 14.86,18.1 13.92,17.16 13.24,17.16 11.91,18.49 9.99,18.49 9.11,17.61 8.87,17.61 8.13,16.87 4.6,16.87 v1(4.34,17.12)
  BOTTOM w0.152: R26.2 v1(2.79,26.16) 2.3,25.67 2.3,22.71 3.43,21.59 3.43,19.43 4.34,18.52 v1(4.34,17.12)
ADC/PWM: length 39.6
  TOP w0.152: U1.L14 20.08,26.71 20.08,28.31 19.74,28.65 19,28.65 18.44,28.09 16.26,28.09 15.34,29.01 12.37,29.01 v1(12.32,28.96) ; J3.7 3.66,6.99 v1(3.66,15.14)
  BOTTOM w0.152: v1(12.32,28.96) 12.32,28.7 8.38,24.77 8.38,24.38 6.86,22.86 5.84,22.86 5.49,22.5 5.49,16.28 4.7,15.49 4.01,15.49 v1(3.66,15.14)
BOOT_MODE0: length 7.3
  TOP w0.152: U1.F11 16.5,25.04 12.8,25.04 R1.2 R4.1
BOOT_MODE1: length 4.6
  TOP w0.152: U1.G14 17.46,27.12 16.81,27.76 15.93,27.76 v1(15.49,28.19)
  BOTTOM w0.152: R2.2 R5.1 15.75,28.45 v1(15.49,28.19)
CAN2_RX/QT2_T3: length 46.3
  TOP w0.152: v2(13,26.47) 13.44,26.04 U1.A13 ; v1(23.75,10.08) 21.56,10.08 21.21,10.44 17.6,10.44 16.67,11.37 16.67,11.98 16.15,12.5 v2(16.15,14.86)
  BOTTOM w0.152: v2(13,26.47) 12.5,26.47 11,24.97 11,23.83 8.26,21.08 8.26,16 8.76,15.49 10.46,15.49 11.13,16.15 14.86,16.15 v2(16.15,14.86) ; v1(23.75,10.08) 24.84,8.99 31.06,8.99 32.8,10.73 32.8,11.5 J5.4
CAN2_TX: length 49
  TOP w0.152: v1(32.77,13.84) 32.77,16.54 J5.2 ; v2(12.62,25.98) 13.22,25.39 U1.A12 ; v1(24.64,10.08) 24.38,10.08 23.95,10.52 21.62,10.52 21.26,10.87 21.01,10.87 20.19,11.68 18.31,11.68 18.11,11.48 17.27,11.48 17.02,11.73 17.02,12.22 16.59,12.65 16.59,15.16 v2(16.26,15.49)
  BOTTOM w0.152: v1(24.64,10.08) 25.43,9.3 28.45,9.3 28.98,9.83 28.98,10.52 29.77,11.3 30.73,11.3 32.77,13.34 v1(32.77,13.84) ; v2(16.26,15.49) 16.26,15.59 15.33,16.51 10.95,16.51 10.27,15.83 8.94,15.83 8.76,16 8.76,17.25 11.38,19.86 11.38,24.74 v2(12.62,25.98)
CSI_D2: length 26.3
  TOP w0.102: 15.48,39.09 16.2,39.09 U5.F5
  TOP w0.152: U5.F5 17.02,39.91 17.02,40.23 16.87,40.39 v2(15.77,40.39) ; U1.J14 18.76,27.21 v2(19.07,27.52) ; v2(14.01,38.65) 14.92,38.65 15.37,39.09 15.48,39.09
  BOTTOM w0.152: v2(19.07,27.52) 19.07,27.54 18.8,27.81 18.8,32.59 18.57,32.82 18.57,34.14 19.02,34.59 19.02,36.55 16.99,38.58 16.81,38.58 16.46,38.94 16.46,39.52 15.77,40.21 v2(15.77,40.39) ; v2(14.01,38.65) 14.15,38.51 14.15,35.59 12.98,34.42 J8.8
CSI_D3: length 28.2
  TOP w0.152: U1.G12 v2(17.13,25.71) ; U5.F2 19.64,40.13 20.57,40.13 20.85,39.85 v2(20.85,39.55) ; v2(16.46,28.5) 16.53,28.42 18.18,28.42 18.71,28.96 20.09,28.96 v2(20.6,28.45)
  BOTTOM w0.152: J7.7 21.97,37 21.97,39.19 21.62,39.55 v2(20.85,39.55) 20.86,39.54 20.86,38.63 21.36,38.13 21.36,36.68 22,36.04 22,33.93 21.39,33.32 21.39,31.42 20.6,30.63 v2(20.6,28.45) ; v2(16.46,28.5) 16.46,27.4 17.13,26.73 v2(17.13,25.71)
CSI_D4: length 22.3
  TOP w0.152: J8.5 12.97,37.54 14.83,37.54 15.26,37.97 U5.D6 15.78,38.18 15.93,38.33 16.26,38.33 16.36,38.23 16.36,38 16.51,37.85 16.74,37.85 16.89,38 v2(16.89,38.12) ; v2(17.78,25.06) U1.H11
  BOTTOM w0.152: v2(16.89,38.12) 16.66,38.12 16.51,37.96 16.51,37.72 16.69,37.54 16.69,37.29 16.51,37.11 16.51,34.16 15.82,33.48 15.82,32.13 15.37,31.67 15.37,31.39 15.52,31.24 16,31.24 16.26,31.5 16.61,31.5 16.89,31.22 16.89,27.4 17.58,26.72 17.58,25.26 v2(17.78,25.06)
CSI_D5: length 23.8
  TOP w0.102: 20.07,39.09 19.53,39.09 19.38,38.94 19.38,38.56 19.78,38.16 U5.D1
  TOP w0.152: 20.07,39.09 20.47,39.09 20.83,38.73 21.56,38.73 22.33,39.5 J7.4 ; U1.H12 v2(18.43,25.71) ; v2(17.4,37.08) 17.58,36.91 17.88,36.91 17.98,37.01 17.98,37.29 18.14,37.44 18.57,37.44 18.67,37.34 18.67,37.03 18.8,36.91 19.28,36.91 19.35,36.98 19.35,37.46 19.78,37.89 U5.D1
  BOTTOM w0.152: v2(18.43,25.71) 18.14,25.71 17.98,25.86 17.98,26.74 17.3,27.43 17.3,31.47 16.89,31.88 16.89,32.26 17.14,32.51 17.14,32.88 16.99,33.04 16.66,33.04 16.51,33.19 16.51,33.49 16.66,33.65 16.99,33.65 17.14,33.8 17.14,34.42 16.89,34.67 16.89,36.93 17.04,37.08 v2(17.4,37.08)
CSI_D6: length 24.1
  TOP w0.152: v2(13.26,35.31) 13.41,35.15 13.41,31.59 13.63,31.37 14.02,31.37 14.17,31.22 14.17,30.78 14.33,30.63 14.63,30.63 14.78,30.78 14.78,31.22 14.94,31.37 15.24,31.37 15.39,31.22 15.39,30.91 15.54,30.76 15.85,30.76 16,30.91 16,31.22 16.15,31.37 16.79,31.37 16.99,31.17 16.99,30.02 17.58,29.44 v2(17.75,29.44) ; U5.E6 15.45,38.72 14.63,37.9 13.54,37.9 v2(13.35,38.09) ; U1.J13 v2(18.43,26.36)
  BOTTOM w0.152: J8.7 13.19,36.6 13.19,37.93 v2(13.35,38.09) 13.54,37.9 13.54,36.31 13.26,36.03 v2(13.26,35.31) ; v2(17.75,29.44) 17.75,27.4 18.43,26.73 v2(18.43,26.36)
CSI_D7: length 21.9
  TOP w0.152: v2(20.6,27.69) 20.4,27.48 20.4,26.38 U1.L13 ; v2(21.79,32.02) 21.23,32.02 21.08,31.86 21.08,31.27 21.23,31.11 22.21,31.11 22.37,31.27 22.37,33.62 21.72,34.26 21.72,35.59 20.22,37.08 20.22,38.15 19.78,38.59 U5.E1 20.21,38.72 20.5,38.43 23.08,38.43 J7.5
  BOTTOM w0.152: v2(20.6,27.69) 20.88,27.69 21.03,27.84 21.03,30.56 21.79,31.32 v2(21.79,32.02)
CSI_D8: length 31.7
  TOP w0.152: U1.M13 21.03,26.36 21.03,28.59 20.29,29.34 18.66,29.34 18.05,28.73 16.84,28.73 16.66,28.91 16.26,28.91 15.57,29.59 14.71,29.59 v1(13.56,30.73) 12.83,30.73 11.53,29.44 10.62,29.44 10.46,29.59 10.46,30.25 10.62,30.4 11.02,30.4 11.18,30.55 11.18,30.86 11.02,31.01 10.62,31.01 10.46,31.16 10.46,32.82 10.8,33.15 J8.9 ; v2(14.45,39.05) 14.87,39.47 U5.F6
  BOTTOM w0.152: v2(14.45,39.05) 14.45,35.28 13.56,34.39 v1(13.56,30.73)
CSI_D9: length 24
  TOP w0.152: v2(19.48,28.24) 19.1,28.24 17.78,26.92 17.78,26.36 U1.H13 ; v2(20.32,39.75) 20.3,39.77 20.08,39.77 U5.F1
  BOTTOM w0.152: v2(19.48,28.24) 19.48,30.81 20.37,31.7 20.37,33.54 20.04,33.87 20.04,34.1 19.74,34.4 19.74,36.88 19.56,37.06 19.24,37.06 18.54,37.76 18.54,38.05 18.11,38.48 18.11,39.14 18.42,39.45 19.89,39.45 20.19,39.75 v2(20.32,39.75) 20.32,39.8 20.47,39.95 21.77,39.95 22.33,39.4 22.33,37.91 J7.6
CSI_FSIN: length 60.1
  TOP w0.152: U5.A4 16.08,34.42 v2(16,34.42) 16.26,34.16 R31.1 ; v1(30.99,28.57) 31.28,28.86 31.28,29.43 30.61,30.1 29.97,30.1 29.74,29.87 28.63,29.87 27.84,29.08 21.08,29.08 20.4,29.77 18.66,29.77 17.92,29.03 16.99,29.03 16.71,29.31 v2(16.46,29.31) ; v2(20.32,43.31) 21.59,42.04 J7.2
  BOTTOM w0.152: J5.3 32.05,17 32.05,21.67 30.77,22.95 30.77,24.47 31.5,25.2 31.5,28.07 v1(30.99,28.57) ; v2(16.46,29.31) 16.46,30.53 16.13,30.86 15.32,30.86 14.91,31.27 14.91,33.32 v2(16,34.42) 16.15,34.57 16.15,39.4 14.99,40.56 14.99,43.18 15.24,43.43 20.19,43.43 v2(20.32,43.31)
CSI_HSYNC: length 26.3
  TOP w0.152: v2(17.4,37.62) 17.39,37.62 16.73,36.96 16.27,36.96 U5.B6 14.86,35.55 v2(14.86,35.51) ; v2(19.08,25.06) 19.08,24.41 U1.K10
  BOTTOM w0.102: 19.08,26.85 19.08,25.35 19.08,25.35 v2(19.08,25.06)
  BOTTOM w0.152: v2(14.86,35.51) 14.94,35.59 14.94,39.23 13.39,40.77 J8.3 ; v2(17.4,37.62) 17.4,37.62 18.06,36.96 18.06,36.73 17.91,36.58 17.45,36.58 17.3,36.42 17.3,34.82 17.61,34.51 17.61,34.3 17.45,34.14 17.45,32.03 17.58,31.9 18.31,31.9 18.47,31.75 18.47,27.55 19.08,26.94 19.08,26.85
CSI_MCLK: length 30.8
  TOP w0.152: J7.8 22.58,34.42 22.5,34.34 22.2,34.34 22.02,34.52 22.02,35.23 22.35,35.56 22.35,36.02 22.2,36.17 21.67,36.17 21.51,36.32 21.51,36.63 21.67,36.78 22.2,36.78 22.35,36.93 22.35,38 22.23,38.12 21.94,38.12 21.79,37.97 21.79,37.33 21.68,37.21 21.34,37.21 21.21,37.34 21.21,38 21.08,38.13 20.68,38.13 20.6,38.05 v2(20.6,37.36) ; U1.K12 v2(19.73,25.71) ; U5.F3 v2(18.58,39.07)
  BOTTOM w0.152: v2(19.73,25.71) 19.84,25.71 20.29,26.16 20.29,26.54 19.89,26.95 19.89,30.78 20.73,31.62 20.73,33.58 21.31,34.16 21.31,35.76 20.6,36.47 v2(20.6,37.36) 19.3,37.36 18.85,37.82 18.85,38.18 19.02,38.35 20.32,38.35 20.46,38.49 20.46,38.89 20.28,39.07 v2(18.58,39.07)
CSI_PIXCLK: length 24.8
  TOP w0.102: 15.47,37.59 16.87,37.59 17.27,37.99 17.27,38.61 U5.E4
  TOP w0.152: U5.E4 17.71,38.39 17.71,37.94 17.88,37.77 18.26,37.77 18.34,37.85 18.34,38.18 18.49,38.33 18.87,38.33 v2(19.23,37.97) ; J8.6 14.73,36.96 15.37,37.59 15.47,37.59 ; U1.L12 v2(20.38,25.71)
  BOTTOM w0.152: v2(19.23,37.97) 20.75,37.97 21.06,37.67 21.06,36.5 21.67,35.89 21.67,34.06 21.06,33.45 21.06,31.52 20.19,30.66 20.19,27.48 20.65,27.03 20.65,25.98 v2(20.38,25.71)
CSI_PWDN: length 28.8
  TOP w0.152: v2(21.34,39.14) 21.34,40.51 21.59,40.77 J7.3 ; U1.M12 v2(21.03,25.71) ; R21.2 21.94,33.27 v2(21.95,33.27) 21.95,33.55 21.34,34.16 21.34,35.48 19.78,37.04 U5.C1
  BOTTOM w0.152: v2(21.03,25.71) 21.03,27 21.34,27.31 21.34,30.15 21.49,30.3 21.74,30.3 21.89,30.15 21.89,29.72 22.05,29.57 22.35,29.57 22.5,29.72 22.5,30.15 22.66,30.3 23.72,30.3 23.88,30.45 23.88,30.93 23.72,31.08 22.55,31.08 22.37,31.27 22.37,32.85 v2(21.95,33.27) 21.95,33.38 22.3,33.73 22.3,36.22 21.67,36.86 21.67,38.81 v2(21.34,39.14)
CSI_RSTB: length 27.8
  TOP w0.152: U1.L11 v2(20.38,25.06) ; U5.A2 18.98,33.78 v2(18.97,33.78)
  BOTTOM w0.102: 19.11,28.54 19.08,28.5 19.08,27.99 19.18,27.89 19.33,27.89 19.61,27.61 19.61,26.82 19.33,26.54 19.33,25.61 19.59,25.35 20.09,25.35 v2(20.38,25.06)
  BOTTOM w0.152: 19.11,28.54 19.11,30.92 20.07,31.88 20.07,33.4 19.69,33.78 R22.2 v2(18.97,33.78) 18.97,34.09 19.35,34.47 19.35,36.59 18.29,37.66 18.29,37.82 17.73,38.38 17.73,39.32 18.16,39.75 19.72,39.75 20.34,40.37 21.44,40.37 22.24,41.17 22.24,42.27 J7.1
CSI_VSYNC: length 23.9
  TOP w0.152: v2(17.78,29.97) 17.78,31.5 17.42,31.85 13.94,31.85 13.79,32 13.79,35.89 v2(13.74,35.94) 13.74,35.97 14.35,36.58 15.14,36.58 U5.C6 ; v2(18.43,25.06) U1.J12
  BOTTOM w0.152: J8.4 12.84,40.06 13.28,40.06 13.44,39.9 13.44,38.57 13.84,38.17 13.84,36.04 v2(13.74,35.94) ; v2(18.43,25.06) 18.82,25.45 18.82,26.77 18.16,27.43 18.16,29.72 17.91,29.97 v2(17.78,29.97)
EP:
  vias: v1(4.45,25.02) v1(4.45,24) v1(5.08,24.51) v1(5.71,25.02) v1(5.71,24)
FLASH_CS: length 23.4
  TOP w0.152: U4.1 17.29,14.86 R14.2 17.27,15.47 17.42,15.62 18.54,15.62 18.69,15.77 18.69,16.54 18.85,16.69 19.15,16.69 19.3,16.54 19.3,15.77 19.46,15.62 19.76,15.62 19.91,15.77 19.91,16.66 20.07,16.81 20.37,16.81 20.52,16.66 20.52,14.63 20.68,14.48 20.98,14.48 21.13,14.63 21.13,16.66 21.29,16.81 21.59,16.81 21.74,16.66 21.74,14.88 21.89,14.73 22.15,14.73 22.31,14.89 22.31,16.81 21.91,17.21 21.91,17.59 22.31,17.99 22.31,18.42 22.16,18.57 21.83,18.57 21.67,18.73 21.67,19.01 21.47,19.21 20.38,19.21 U1.L3
FLASH_D0: length 16.2
  TOP w0.152: U1.P3 22.15,19.54 22.92,18.77 22.92,12.63 22.17,11.89 22.17,11.48 22.43,11.23 23.55,11.23 v1(23.62,11.3)
  BOTTOM w0.152: RN1.4 22.89,11 23.2,11.3 v1(23.62,11.3) 23.62,10.69 23.77,10.54 25.17,10.54 25.3,10.41 25.3,10.06 25.43,9.93 26.04,9.93 26.17,10.06 R15.2
FLASH_D1: length 17.3
  TOP w0.152: U1.N4 21.43,20.11 21.64,20.11 21.88,19.87 22.25,19.87 23.22,18.89 23.22,13.5 23.34,13.39 23.34,12.29 v1(22.76,11.71)
  BOTTOM w0.152: v1(22.76,11.71) 22.24,11.71 22.09,11.56 RN1.3 22.09,10.23 21.79,9.93 20.09,9.93 19.6,9.44 19.6,9.13 19.38,8.92 17.93,8.92 17.78,9.07 R16.2
FLASH_D2: length 18.5
  TOP w0.152: v1(23.62,11.94) 24.03,11.94 24.18,12.09 24.18,12.37 24.03,12.52 23.88,12.52 23.72,12.68 23.72,12.98 23.88,13.13 24.03,13.13 24.18,13.29 24.18,13.59 24.03,13.74 23.88,13.74 23.72,13.9 23.72,14.2 23.88,14.35 24.03,14.35 24.18,14.51 24.18,14.81 24.03,14.96 23.88,14.96 23.72,15.12 23.72,15.42 23.88,15.57 24.03,15.57 24.18,15.72 24.18,15.98 23.53,16.63 23.53,19.02 22.36,20.19 U1.P4
  BOTTOM w0.152: R17.2 19.03,9.38 19.86,10.21 21.14,10.21 21.29,10.36 RN1.2 21.29,11.87 21.59,12.17 23.14,12.17 23.37,11.94 v1(23.62,11.94)
FLASH_D3: length 26.5
  TOP w0.152: v1(25.02,12.32) 24.87,12.47 24.87,12.73 25.02,12.88 25.2,12.88 25.35,13.03 25.35,13.34 25.2,13.49 24.94,13.49 24.79,13.64 24.79,13.94 24.94,14.1 25.2,14.1 25.35,14.25 25.35,14.55 25.2,14.71 24.94,14.71 24.79,14.86 24.79,15.19 24.96,15.35 25.4,15.35 25.55,15.51 25.55,16.11 25.24,16.42 24.6,16.42 24.45,16.57 24.45,16.87 24.6,17.02 25.63,17.02 25.78,17.17 25.78,17.61 25.55,17.84 25.33,17.84 24.99,17.5 24.29,17.5 24.14,17.65 24.14,19.27 22.38,21.02 22.16,21.02 22.01,20.87 U1.P5
  BOTTOM w0.152: R18.2 26.17,13.67 25.83,14.01 25.6,14.01 25.45,13.86 25.45,13.11 25.68,12.88 25.68,11.84 25.38,11.54 25.04,11.54 24.75,11.83 24.75,12.05 v1(25.02,12.32) 24.87,12.47 21.44,12.47 20.49,11.53 RN1.1
FLASH_SCLK: length 2.5
  TOP w0.152: U4.6 27.43,12.32 v1(27.81,11.94)
  BOTTOM w0.152: v1(27.81,11.94) 27.43,12.32 R10.2
LED_B: length 10.2
  TOP w0.152: RN2.1 8.31,28.14 8.69,27.76 8.69,26.49 11,24.18 11,23.52 12.72,21.8 13.87,21.8 U1.B7
LED_G: length 11.8
  TOP w0.152: RN2.3 8.69,29.74 9.32,29.11 9.32,26.8 11.66,24.46 11.66,23.9 13.1,22.46 14.53,22.46 U1.C7
LED_IR: length 7.9
  TOP w0.152: U1.B14 13.43,27.46 12.17,27.46 11.53,28.09 11.05,28.09 8.6,30.54 RN2.4
LED_R: length 9.9
  TOP w0.152: U1.A7 12.92,22.14 11.33,23.72 11.33,24.35 8.99,26.7 8.99,28.52 8.58,28.94 RN2.2
LPSPI1_PCS0: length 22.1
  TOP w0.152: v2(5.97,21.23) 5.97,21.34 7.01,22.38 11.4,22.38 13.26,20.52 14.43,20.52 14.53,20.63 14.53,21.17 U1.C6
  BOTTOM w0.152: J3.4 1.65,13.21 3.05,14.61 3.73,14.61 4.24,15.11 4.93,15.11 5.79,15.98 5.79,21.06 v2(5.97,21.23)
LPSPI1_SCK: length 17.8
  TOP w0.152: v2(5.08,20.19) 5.54,19.74 6.97,19.74 8.3,21.06 10.82,21.06 12.99,18.89 U1.A2
  BOTTOM w0.152: J3.3 2.83,15.15 3.81,16.13 4.7,16.13 5.13,16.56 5.13,20.14 v2(5.08,20.19)
LPSPI1_SDI: length 23.3
  TOP w0.152: v2(5.08,20.83) 5.87,20.04 6.85,20.04 8.17,21.36 10.95,21.36 13.08,19.23 13.69,19.23 13.88,19.42 13.88,19.64 14.1,19.86 16.31,19.86 16.48,19.68 16.48,18.57 U1.E1
  BOTTOM w0.152: J3.2 2.7,16.64 4.62,16.64 4.83,16.84 4.83,18.8 4.57,19.05 4.57,20.45 4.95,20.83 v2(5.08,20.83)
LPSPI1_SDO: length 17
  TOP w0.152: U1.D1 15.17,18.57 14.71,18.57 14.53,18.39 14.53,18.13 14.33,17.93 12.93,17.93 12.06,18.8 9.86,18.8 9.02,17.95 8.78,17.95 8.03,17.2 5.03,17.2 4.37,17.86 v1(3.56,17.86)
  BOTTOM w0.152: v1(3.56,17.86) 1.65,19.76 J3.1
RST_B: length 39.2
  TOP w0.152: v1(32.13,16.13) 32.13,18.45 J5.1 ; J1.4 31.24,11.46 31.24,5.33 29.59,3.68 C26.1 C28.1 R6.2 31.62,4 v1(31.53,4.1) ; U1.M7 21.03,21.81 22.15,21.81 22.3,21.66 22.3,21.56 24.44,19.42 24.44,18.18 24.61,18.01 v1(24.89,18.01)
  BOTTOM w0.152: v1(24.89,18.01) 25.25,18.01 25.64,17.63 27.33,17.63 28.96,16 28.96,13.75 J1.4 32.13,14.64 v1(32.13,16.13) ; v1(31.53,4.1) 31.56,4.06 SW1.2
SCCB_SCL: length 44.6
  TOP w0.152: v1(9.8,16.4) 9.8,16.58 10.49,17.27 11.3,17.27 12.61,15.96 14.37,15.96 15.58,17.17 17.18,17.17 18.11,18.1 U1.H1 ; U5.A5 16.58,35.38 16.13,34.92 15.62,34.92 v2(15.11,34.42) 15.37,34.16 R23.2
  BOTTOM w0.152: J8.1 13.08,43.31 13.34,43.05 13.34,41.78 15.75,39.37 15.75,35.05 v2(15.11,34.42) 14.5,33.81 14.5,30.51 14.1,30.1 14.1,26.31 12.22,24.43 12.22,19.2 9.8,16.79 v1(9.8,16.4)
SCCB_SDA: length 46.2
  TOP w0.152: U5.B5 16.18,36.07 16.18,35.51 15.98,35.31 15.37,35.31 14.99,34.92 14.81,34.92 v2(14.3,34.42) 14.55,34.16 R24.2 ; U1.G3 17.78,19.21 17.78,18.13 17.07,17.42 15.4,17.42 14.25,16.27 12.74,16.27 11.43,17.58 10.37,17.58 9.22,16.43 v1(9.22,16.26)
  BOTTOM w0.152: J8.2 12.62,42.04 15.37,39.29 15.37,35.31 14.99,34.92 14.81,34.92 v2(14.3,34.42) 14.1,34.21 14.1,30.61 13.72,30.23 13.72,26.42 11.84,24.54 11.84,19.46 9.22,16.84 v1(9.22,16.26)
SD_CD: length 27
  TOP w0.152: v1(10.43,16.59) 10.29,16.45 10.29,16.18 9.78,15.67 9.78,14.27 10.87,13.19 RN3.8 10.44,12.7 10.29,12.55 10.29,9.5 11.91,7.87 13.05,7.87 v1(14.38,6.55) ; U1.D13 v2(15.18,25.71)
  BOTTOM w0.152: J6.10 v1(14.38,6.55) ; v1(10.43,16.59) 12.6,18.76 12.6,24.33 13.98,25.71 v2(15.18,25.71)
SD_CLK: length 20
  TOP w0.152: U1.J3 v2(18.43,19.21)
  BOTTOM w0.152: J6.5 8.48,11.84 8.36,11.71 8.08,11.71 7.92,11.56 7.92,11.2 8.08,11.05 13.06,11.05 13.84,11.84 13.84,13.94 14,14.1 14.44,14.1 15,13.54 16.18,13.54 17.04,14.4 17.04,16.64 18.43,18.02 v2(18.43,19.21)
SD_CMD: length 20.6
  TOP w0.152: v1(13.34,13.67) 13.26,13.6 RN3.5 ; U1.J4 v2(18.43,19.86)
  BOTTOM w0.152: J6.3 10.68,11.54 10.85,11.38 11.48,11.38 11.64,11.53 11.64,11.75 11.79,11.9 12.09,11.9 12.25,11.75 12.25,11.53 12.4,11.38 12.83,11.38 13.51,12.06 13.51,13.49 v1(13.34,13.67) 13.34,14.3 13.64,14.61 13.64,14.81 13.79,14.96 14.1,14.96 14.25,14.81 14.25,14.61 14.4,14.45 14.51,14.45 15.07,13.89 16.1,13.89 16.74,14.53 16.74,16.13 16.59,16.28 16.23,16.28 16.08,16.43 16.08,16.84 16.21,16.97 16.81,16.97 18.03,18.19 18.03,19.47 v2(18.43,19.86)
SD_D0: length 20.3
  TOP w0.152: R29.2 v1(6.27,13.69) ; v1(13.13,14.78) 13.13,14.4 13.28,14.25 13.52,14.25 13.89,14.61 13.89,15.14 14.04,15.29 14.56,15.29 15.88,16.61 17.41,16.61 18.76,17.96 U1.J1
  BOTTOM w0.152: J6.7 6.28,13.68 v1(6.27,13.69) 6.27,14.2 6.43,14.35 7.86,14.35 8.01,14.2 8.01,13.87 8.16,13.72 8.47,13.72 8.62,13.87 8.62,14.2 8.77,14.35 9.96,14.35 10.11,14.2 10.11,13.77 10.26,13.61 10.57,13.61 10.72,13.77 10.72,14.27 10.83,14.39 11.34,14.39 11.48,14.53 11.48,15.04 11.63,15.19 12.98,15.19 13.13,15.04 v1(13.13,14.78)
SD_D1: length 21.1
  TOP w0.152: R28.2 5.21,11.71 v1(5.18,11.68) ; U1.K1 19.33,18.17 19.33,17.67 17.66,16 16.14,16 14.3,14.16 v1(14.3,13.63)
  BOTTOM w0.152: J6.8 v1(5.18,11.68) 5.21,11.68 6.22,10.67 13.21,10.67 14.15,11.61 14.15,13.47 v1(14.3,13.63)
SD_D2: length 20.7
  TOP w0.152: RN3.7 11.67,13.49 v1(11.84,13.67) 11.84,13.94 11.68,14.1 11.44,14.1 11.29,13.94 11.29,13.83 11.11,13.65 10.88,13.65 10.26,14.27 10.26,14.51 10.41,14.66 11.07,14.66 11.23,14.82 11.23,15.12 11.07,15.27 10.46,15.27 10.31,15.43 10.31,15.7 10.46,15.85 10.97,15.85 11.07,15.95 11.07,16.26 11.2,16.38 11.53,16.38 11.68,16.23 11.68,15.81 11.84,15.66 14.5,15.66 15.76,16.92 17.28,16.92 18.43,18.06 18.43,18.56 U1.H2
  BOTTOM w0.152: J6.1 12.88,14.23 12.64,14.48 12.32,14.48 11.84,14 v1(11.84,13.67)
SD_D3: length 19.6
  TOP w0.152: v1(12.43,13.61) 12.46,13.58 RN3.6 12.46,12.09 12.62,11.94 13.54,11.94 13.84,11.63 13.84,10.06 14,9.91 14.33,9.91 14.48,10.06 14.48,11.38 14.63,11.53 14.86,11.53 15.01,11.68 15.01,11.99 14.86,12.14 14.63,12.14 13.87,12.9 13.87,14.16 16.01,16.31 17.54,16.31 19.08,17.85 19.08,18.56 U1.J2
  BOTTOM w0.152: J6.2 11.78,12.98 12.42,13.61 v1(12.43,13.61)
SWD_CLK: length 22.5
  TOP w0.152: U1.F12 v2(17.13,25.06) ; v2(24.21,26.31) 23.8,25.91 23.8,23.37 24.31,22.86 24.31,21.72 24.92,21.11 25.3,21.11 25.58,20.83 25.58,19.65 25.32,19.39 25.32,18.49 25.69,18.13 v1(25.87,18.13)
  BOTTOM w0.152: v2(24.21,26.31) 24.18,26.31 23.58,25.71 23.17,25.71 22.28,24.82 21.32,24.82 21.19,24.68 17.51,24.68 v2(17.13,25.06) ; v1(25.87,18.13) 25.92,18.08 28.68,18.08 29.08,17.69 J1.2
SWD_DIO: length 26.1
  TOP w0.152: v2(15.83,27.01) U1.E14 ; v2(27.86,17.68) 27.51,18.03 26.45,18.03 26.3,18.19 26.3,18.91 25.91,19.3 25.91,21.59 25.43,22.07 24.71,22.07 24.61,22.17 24.61,23.01 24.26,23.37 v2(24.26,25.76)
  BOTTOM w0.152: J1.3 30.1,16.03 28.45,17.68 v2(27.86,17.68) ; v2(24.26,25.76) 24.1,25.76 23.75,25.4 23.29,25.4 22.32,24.43 17.23,24.43 16.71,24.94 16.71,25.98 16.87,26.14 16.87,26.57 16.42,27.01 v2(15.83,27.01)
SWD_SWO: length 62.2
  TOP w0.152: v1(31.75,8.64) 32.26,9.14 32.26,13.72 31.67,14.3 31.67,18.65 J1.1 ; v1(23.75,9.4) 21.69,9.4 21.01,10.08 17.4,10.08 16.28,11.2 16.28,11.91 15.72,12.47 v2(15.72,14.4) ; U1.G13 17.13,26.36 17.13,26.8 16.49,27.43 14.61,27.43 13.69,28.35 12.85,28.35 12.45,27.94 v2(12.32,27.94)
  BOTTOM w0.152: v1(23.75,9.4) 24.51,8.64 v1(31.75,8.64) ; v2(15.72,14.4) 15.72,14.68 14.61,15.8 11.2,15.8 10.59,15.19 8.51,15.19 7.87,15.82 7.87,21.34 10.64,24.1 10.64,25.27 12.32,26.95 v2(12.32,27.94)
UART4_RX/QT2_T1: length 63.4
  TOP w0.152: v1(32.26,1.14) 32.38,1.27 32.38,8.54 J5.5 ; U1.A3 13.23,19.54 11.1,21.67 7.29,21.67 7.05,21.42 7.05,20.94 v2(6.63,20.52)
  BOTTOM w0.152: v2(6.63,20.52) 6.43,20.32 6.43,15.32 5.46,14.35 4.76,14.35 4.19,13.78 3.62,13.78 3.15,13.31 3.15,10.79 8.79,5.16 16.54,5.16 20.8,0.89 32,0.89 v1(32.26,1.14)
UART4_TX/QT2_T0: length 63.5
  TOP w0.152: v1(33.02,1.14) 32.77,1.4 32.77,6.38 J5.6 ; v2(6.62,21.22) 6.62,21.5 7.09,21.97 11.3,21.97 13.43,19.84 13.64,19.84 13.99,20.19 U1.B4
  BOTTOM w0.152: v1(33.02,1.14) 32.46,0.58 20.62,0.58 16.36,4.85 8.66,4.85 2.79,10.72 2.79,13.59 3.43,14.22 3.94,14.22 4.45,14.73 5.21,14.73 6.1,15.62 6.1,20.71 6.61,21.22 v2(6.62,21.22)
USB1_DN: length 8.4
  TOP w0.152: U1.M8 v2(21.03,23.11)
  BOTTOM w0.15: R12.2 27.35,23.71 27.35,23.57 27.2,23.42 22.69,23.42 21.91,22.63 21.02,22.63 20.86,22.79 20.86,22.94 v2(21.03,23.11)
USB1_DP: length 9.4
  TOP w0.152: U1.L8 v2(20.38,23.11)
  BOTTOM w0.15: R11.2 27.69,23.75 27.69,23.43 27.34,23.09 22.83,23.09 22.04,22.3 20.88,22.3 20.53,22.65 20.53,22.96 v2(20.38,23.11)
USB_5V: length 6.6
  TOP w0.254: U1.N6 v2(21.68,21.16)
  BOTTOM w0.381: v1(26.92,22.48) v1(26.16,22.48) 26.04,22.35 24.17,22.35 24,22.52 23.05,22.52 22.3,21.77 C35.1 21.97,21.45 v2(21.68,21.16)
  vias: v2(21.84,7.62) v2(21.84,6.99) v2(22.73,7.62) v2(22.73,6.99)
USB_OTG1_ID: length 17
  TOP w0.152: U1.H10 v2(17.78,23.76)
  BOTTOM w0.152: v2(17.78,23.76) 18.19,24.17 21.97,24.17 22.22,23.93 25.76,23.93 25.91,24.08 25.91,27.25 26.29,27.63 28.39,27.63 28.7,27.94 R32.2 R33.1
USER BUTTON: length 45.6
  TOP w0.152: U1.L6 20.36,21.18 20.36,20.65 20.48,20.53 22.45,20.53 23.83,19.14 23.83,16.76 24.49,16.1 24.49,11.96 24.64,11.81 24.99,11.81 25.15,11.66 25.15,9.78 24.31,8.94 21.72,8.94 20.88,9.78 17.14,9.78 15.9,11.02 15.9,11.81 15.13,12.59 v2(15.13,14.42) ; v1(6.93,17.65) 7.11,17.83 7.59,17.83 8.47,18.71 SW2.1 8.53,19.31 C27.1 R30.2
  BOTTOM w0.152: v2(15.13,14.42) 15.13,14.72 14.35,15.49 11.43,15.49 10.77,14.83 7.75,14.83 6.73,15.85 6.73,17.45 v1(6.93,17.65)
N80926: length 10.5
  TOP w0.152: U1.K8 19.73,22.46 22.37,22.46 22.58,22.25 22.58,21.71 24.75,19.55 24.75,18.81 v1(24.89,18.67)
  BOTTOM w0.305: C39.1 23.39,18.27 C38.1 24.4,18.67 v1(24.89,18.67)
